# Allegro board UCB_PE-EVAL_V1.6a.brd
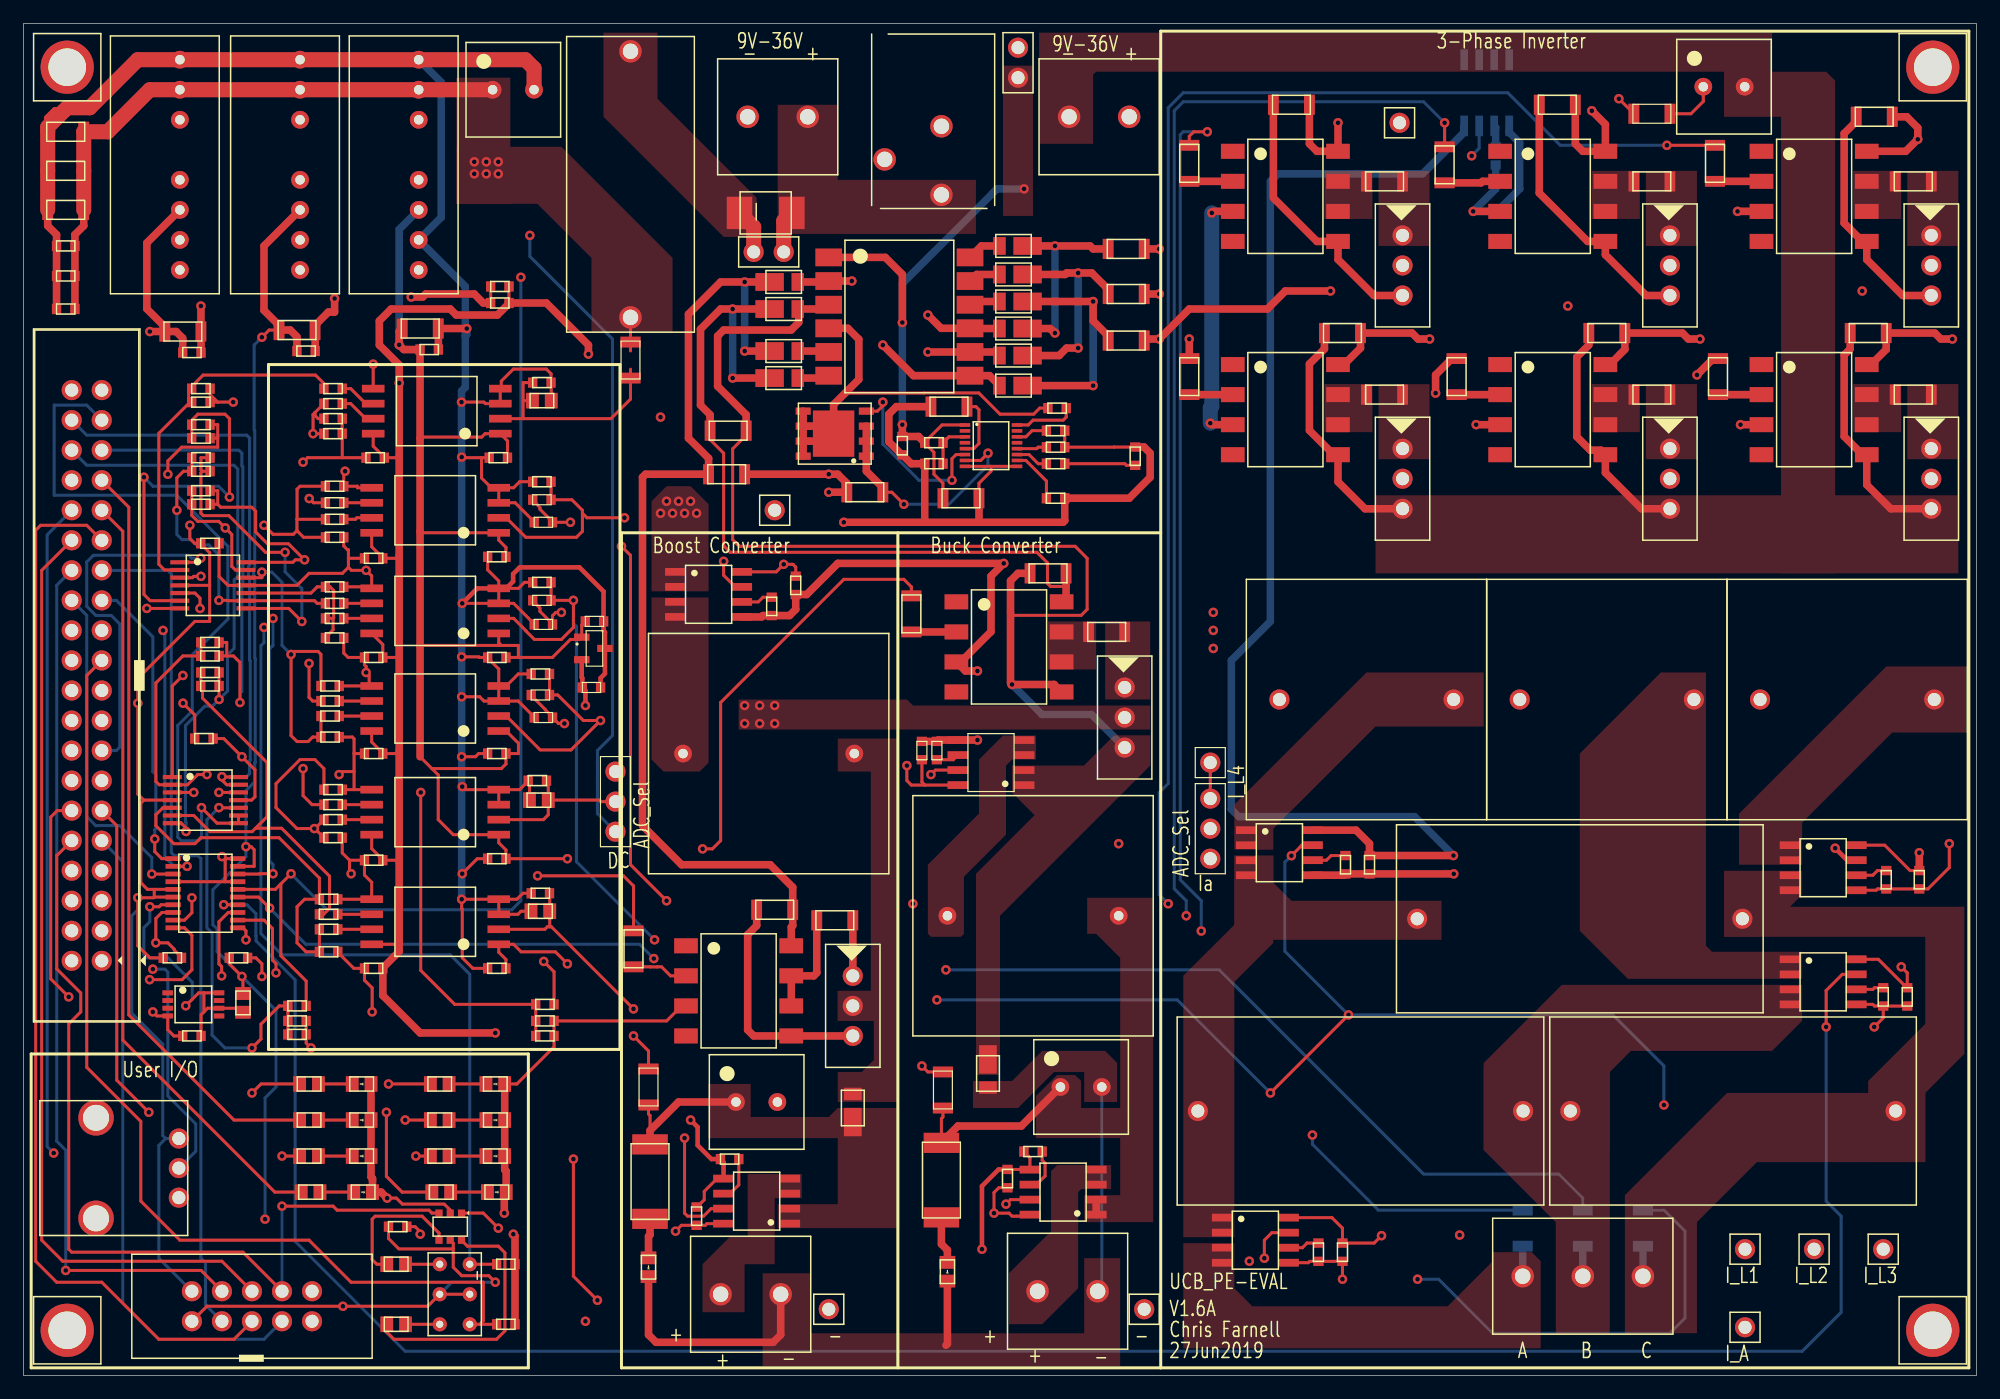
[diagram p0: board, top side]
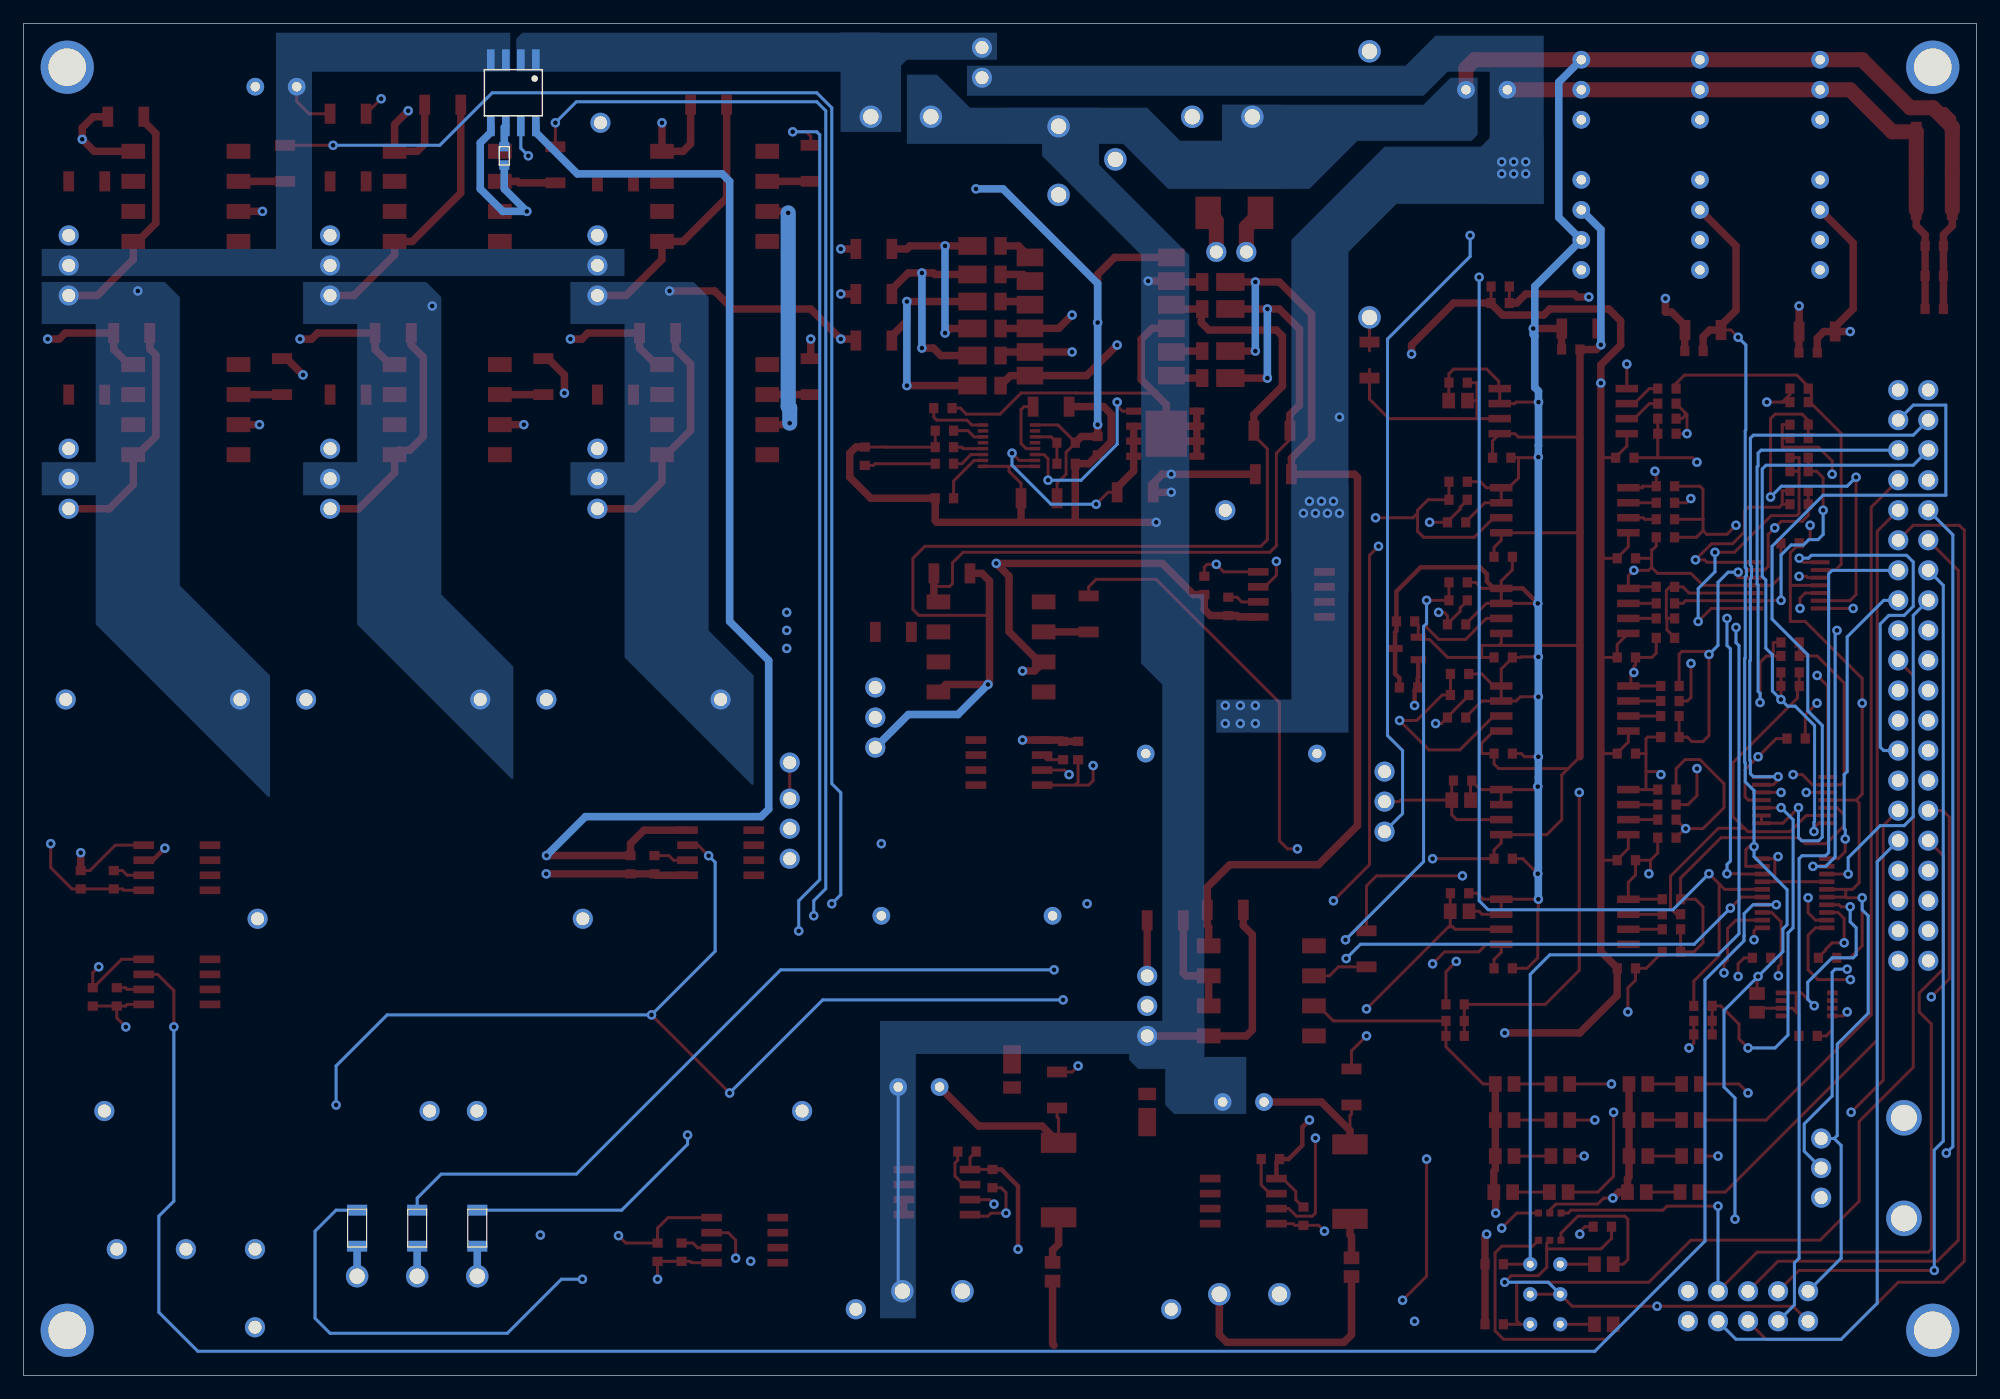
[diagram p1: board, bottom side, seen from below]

Outline 165.1 x 114.3 mm; copper layers: TOP, LAYER2, LAYER3, BOTTOM. Coordinates in mm from the lower left corner of the outline.
Outline path: 0,114.3 165.1,114.3 165.1,0 0,0 0,114.3

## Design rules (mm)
constraint set DEFAULT: min track width 0.254

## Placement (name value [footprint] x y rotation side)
ADC1  AD7928BRUZ  [20-TSSOP]  15.37 40.77 0 top
C1  10uF  [ECQ-E2106KFB]  113.03 22.35 0 top
C2  10uF  [ECQ-E2106KFB]  144.53 22.35 0 top
C3  10uF  [ECQ-E2106KFB]  131.57 38.61 0 top
C4  100uF  [UVZ1H101MPD]  89.41 24.38 0 top
C5  100uF  [UVZ1H101MPD]  41.4 108.71 0 top
C16  10uF  [C_1206]  79.25 74.17 0 top
C17  1uF  [C_0603]  74.3 78.61 270 top
C18  4.7uF  [C_1206]  78.23 81.91 180 top
C19  2.2nF  [C_0603]  87.25 74.17 180 top
C20  4.7nF  [C_0603]  93.98 77.72 270 top
C21  10uF  [C_1206]  93.22 87.5 0 top
C22  10uF  [C_1206]  93.22 91.44 0 top
C23  10uF  [C_1206]  93.22 95.25 0 top
C24  10uF  [C_1206]  59.56 79.88 0 top
C25  10uF  [C_1206]  59.44 76.2 0 top
C26  10uF  [C_1206]  3.56 105.16 180 top
C27  10uF  [C_1206]  3.56 101.85 180 top
C28  10uF  [C_1206]  13.46 88.26 0 top
C29  10uF  [C_1206]  23.11 88.39 0 top
C30  1uF  [C_0603]  3.56 92.96 180 top
C31  1uF  [C_0603]  3.56 95.5 180 top
C32  1uF  [C_0603]  23.88 86.61 0 top
C33  1uF  [C_0603]  14.22 86.49 0 top
C34  100uF  [UVZ1H101MPD]  143.76 108.97 0 top
C35  100uF  [UVZ1H101MPD]  61.98 23.11 0 top
C36  4.7uF  [C_1206]  107.19 107.44 180 top
C37  4.7uF  [C_1206]  129.67 107.44 180 top
C38  4.7uF  [C_1206]  156.46 106.43 180 top
C39  4.7uF  [C_1206]  86.61 67.82 180 top
C40  4.7uF  [C_1206]  111.51 88.14 180 top
C41  4.7uF  [C_1206]  133.86 88.14 180 top
C42  4.7uF  [C_1206]  155.96 88.14 180 top
C43  4.7uF  [C_1206]  63.5 39.37 180 top
C44  0.1uF  [C_0603]  111.51 10.41 270 top
C45  0.1uF  [C_0603]  160.27 41.91 270 top
C46  0.1uF  [C_0603]  159.26 32 270 top
C47  1nF  [C_0603]  109.47 10.41 270 top
C48  1nF  [C_0603]  111.76 43.18 270 top
C49  1nF  [C_0603]  157.23 32 270 top
C50  1nF  [C_0603]  85.34 18.92 180 top
C51  1nF  [C_0603]  59.69 18.29 180 top
C52  0.1uF  [C_0603]  83.19 16.64 90 top
C53  0.1uF  [C_0603]  56.9 13.46 90 top
C54  10uF  [C_1206]  3.56 98.55 180 top
C55  10uF  [C_1206]  33.53 88.52 0 top
C56  1uF  [C_0603]  3.56 90.17 180 top
C57  1uF  [C_0603]  34.29 86.74 0 top
C58  100pF  [C_0603]  43.81 83.95 0 top
C59  0.1uF  [C_0603]  40.13 77.6 180 top
C60  0.1uF  [C_0603]  29.72 77.6 180 top
C61  100pF  [C_0603]  14.99 82.3 0 top
C62  100pF  [C_0603]  26.16 79.63 180 top
C63  100pF  [C_0603]  43.81 75.56 180 top
C64  0.1uF  [C_0603]  40.01 69.22 180 top
C65  0.1uF  [C_0603]  29.59 69.09 180 top
C66  100pF  [C_0603]  14.99 79.25 0 top
C67  100pF  [C_0603]  26.29 70.87 180 top
C68  100pF  [C_0603]  43.81 67.06 180 top
C69  0.1uF  [C_0603]  40.01 60.71 180 top
C70  0.1uF  [C_0603]  29.59 60.71 180 top
C71  100pF  [C_0603]  14.99 76.45 0 top
C72  100pF  [C_0603]  26.29 62.36 180 top
C73  100pF  [C_0603]  43.69 59.31 180 top
C74  0.1uF  [C_0603]  40.01 52.58 180 top
C75  0.1uF  [C_0603]  29.59 52.58 180 top
C76  100pF  [C_0603]  14.99 73.66 0 top
C77  100pF  [C_0603]  25.91 53.98 180 top
C78  100pF  [C_0603]  43.43 50.29 180 top
C79  0.1uF  [C_0603]  40.01 43.69 180 top
C80  0.1uF  [C_0603]  29.59 43.56 180 top
C81  100pF  [C_0603]  15.75 60.83 0 top
C82  100pF  [C_0603]  26.16 45.47 180 top
C83  100pF  [C_0603]  43.69 40.77 180 top
C84  0.1uF  [C_0603]  40.01 34.42 180 top
C85  0.1uF  [C_0603]  29.59 34.42 180 top
C86  100pF  [C_0603]  15.75 58.29 0 top
C87  100pF  [C_0603]  25.78 35.81 180 top
C88  220pF  [C_0603]  23.11 28.83 0 top
C89  220pF  [C_0603]  44.07 28.7 0 top
C94  1nF  [C_0603]  124.46 103.12 270 bottom
C95  0.1uF  [C_0603]  40.26 92.07 180 top
C96  1uF  [C_0603]  12.57 35.31 0 top
C97  1uF  [C_0603]  18.16 35.31 0 top
C98  1uF  [C_0603]  15.75 70.36 0 top
C99  1uF  [C_0603]  15.24 53.85 0 top
C100  0.1uF  [C_0603]  40.26 90.68 180 top
C102  1uF  [C_0603]  14.22 28.7 0 top
C103  0.1uF  [C_0603]  31.62 12.57 0 top
C104  1nF  [C_0603]  157.48 41.91 270 top
C105  1nF  [C_0603]  63.25 65.02 270 top
C106  0.1uF  [C_0603]  65.28 66.8 270 top
C107  0.1uF  [C_0603]  113.79 43.18 270 top
C108  1nF  [C_0603]  77.22 52.83 90 top
C109  0.1uF  [C_0603]  75.95 52.83 90 top
C110  0.1uF  [C_0603]  48.01 58.17 0 top
C111  0.1uF  [C_0603]  48.26 63.75 0 top
C112  0.1uF  [C_0603]  43.94 72.14 180 top
C113  0.1uF  [C_0603]  43.94 63.5 180 top
C114  0.1uF  [C_0603]  43.94 55.63 180 top
D1  STPS3150U  [DO-214AA_SMB]  62.74 98.3 0 top
D5  DFLS260-7  [POWERDI-123]  83.69 90.81 180 top
D6  DFLS260-7  [POWERDI-123]  83.69 93.09 180 top
D7  DFLS260-7  [POWERDI-123]  83.69 95.5 180 top
D8  DFLS260-7  [POWERDI-123]  64.26 84.33 0 top
D9  DFLS260-7  [POWERDI-123]  64.26 86.61 0 top
D10  DFLZ18-7  [POWERDI-123]  83.69 83.69 180 top
D11  DFLZ18-7  [POWERDI-123]  83.69 86.23 180 top
D12  DFLZ18-7  [POWERDI-123]  83.69 88.52 180 top
D13  DFLZ18-7  [POWERDI-123]  64.26 90.17 0 top
D14  DFLZ18-7  [POWERDI-123]  64.26 92.46 0 top
D15  DFLS260-7  [POWERDI-123]  81.53 25.53 270 top
D16  DFLS260-7  [POWERDI-123]  70.1 22.61 90 top
D17  LED-R  [LED_0805-RED]  78.11 8.76 90 top
D18  LED-G  [LED_0805-GREEN]  52.83 9.14 90 top
D19  LED-G  [LED_0805-GREEN]  40.01 15.49 180 top
D20  LED-Y  [LED_0805-YELLOW]  39.88 18.54 180 top
D21  LED-O  [LED_0805-ORANGE]  39.88 21.59 180 top
D22  LED-R  [LED_0805-RED]  39.88 24.64 180 top
D23  LED-G  [LED_0805-GREEN]  28.7 15.49 180 top
D24  LED-Y  [LED_0805-YELLOW]  28.58 18.54 180 top
D25  LED-O  [LED_0805-ORANGE]  28.58 21.59 180 top
D26  LED-R  [LED_0805-RED]  28.58 24.64 180 top
F1  65600001009  [FUSE_5X20MM]  51.31 100.71 270 top
J1  AWHW 40G-0202-T  [40-IDC-M]  5.33 59.18 180 top
J2  -  [1715721]  63.75 106.43 270 top
J3  -  [1715734]  131.83 8.38 90 top
J4  -  [1715721]  88.27 7.11 90 top
J5  -  [1715721]  61.47 6.86 90 top
J6  PJ-102BH  [DC-PWR_JACK]  77.6 106.17 0 top
J7  AWHW 10G-0202-T  [10-IDC-M]  19.3 5.84 90 top
J8  -  [1715721]  90.93 106.43 270 top
JP1  -  [J_1X2]  84.07 111 180 top
JP2  -  [J_1X2]  62.99 95 270 top
JP3  -  [J_1X3]  100.33 46.23 180 top
JP4  -  [J_1X3]  50.04 48.51 0 top
L1  180uH  [PCV-2-184-05L]  113.54 57.15 0 top
L2  180uH  [PCV-2-184-05L]  133.86 57.15 0 top
L3  180uH  [PCV-2-184-05L]  154.18 57.15 0 top
L4  560uH  [PCV-2-564-02L]  85.34 38.86 0 top
L5  560uH  [PCV-2-564-02L]  62.99 52.58 0 top
MECH1  Mech_Hole  [4-40_SCREW]  3.68 110.62 0 top
MECH2  Mech_Hole  [4-40_SCREW]  3.68 3.81 0 top
MECH3  Mech_Hole  [4-40_SCREW]  161.42 110.62 0 top
MECH4  Mech_Hole  [4-40_SCREW]  161.42 3.81 0 top
PM1  EC4SAW-24S33N  [SIP-8]  22.1 102.36 0 top
PM2  EC4SAW-24S05N  [SIP-8]  11.94 102.36 0 top
PM3  EC4SAW-24S05N  [SIP-8]  32.13 102.36 0 top
Q1  STGP15H60DF  [TO-220]  116.59 93.85 0 top
Q2  STGP15H60DF  [TO-220]  116.59 75.82 0 top
Q3  STGP15H60DF  [TO-220]  139.19 93.85 0 top
Q4  STGP15H60DF  [TO-220]  139.19 75.82 0 top
Q5  STGP15H60DF  [TO-220]  161.29 93.85 0 top
Q6  STGP15H60DF  [TO-220]  161.29 75.82 0 top
Q7  STGP15H60DF  [TO-220]  93.09 55.63 0 top
Q8  STGP15H60DF  [TO-220]  70.1 31.24 0 top
Q9  Si7898DP  [SO-8_PP]  68.58 79.63 180 top
R8  825k  [R_0603]  76.96 78.87 0 top
R9  215k  [R_0603]  76.96 77.09 0 top
R10  133k  [R_0603]  87.25 78.49 180 top
R11  10k  [R_0603]  87.25 77.09 180 top
R12  71.5k  [R_0603]  87.38 81.79 180 top
R13  6.04k  [R_0603]  87.25 79.88 0 top
R14  0.01  [R_1206]  71.12 74.68 0 top
R15  2.49k  [R_2512]  77.6 16.51 270 top
R16  2.49k  [R_2512]  52.96 16.38 270 top
R17  120  [R_1206]  98.55 102.49 270 top
R18  10  [R_1206]  115.06 100.97 0 top
R19  120  [R_1206]  120.14 102.36 270 top
R20  10  [R_1206]  137.67 100.97 0 top
R21  120  [R_1206]  143 102.49 270 top
R22  10  [R_1206]  159.77 100.97 0 top
R23  120  [R_1206]  75.06 64.39 270 top
R24  10  [R_1206]  91.57 62.87 0 top
R25  120  [R_1206]  98.55 84.46 270 top
R26  10  [R_1206]  115.06 82.93 0 top
R27  120  [R_1206]  121.16 84.46 270 top
R28  10  [R_1206]  137.67 82.93 0 top
R29  120  [R_1206]  143.26 84.46 270 top
R30  10  [R_1206]  159.77 82.93 0 top
R31  120  [R_1206]  51.56 36.07 270 top
R32  10  [R_1206]  68.58 38.48 0 top
R33  1Meg  [R_1206]  51.31 85.85 270 top
R35  10k  [R_0603]  26.16 82.17 180 top
R36  10k  [R_0603]  26.16 83.44 180 top
R37  10k  [R_0603]  26.16 80.9 180 top
R38  10k  [R_0603]  14.99 83.44 0 top
R39  31.6k  [R_0805]  43.81 82.42 0 top
R40  1Meg  [R_1206]  126.75 12.45 90 bottom
R41  10k  [R_0603]  26.29 72.39 180 top
R42  10k  [R_0603]  26.29 73.79 180 top
R43  10k  [R_0603]  26.29 75.18 180 top
R44  10k  [R_0603]  14.99 80.39 0 top
R45  13.7k  [R_0603]  43.81 74.04 180 top
R46  1Meg  [R_1206]  131.83 12.45 90 bottom
R47  10k  [R_0603]  26.29 64.01 180 top
R48  10k  [R_0603]  26.29 65.28 180 top
R49  10k  [R_0603]  26.29 66.68 180 top
R50  10k  [R_0603]  14.99 77.6 0 top
R51  13.7k  [R_0603]  43.81 65.53 180 top
R52  1Meg  [R_1206]  136.91 12.45 90 bottom
R53  10k  [R_0603]  25.91 55.75 180 top
R54  10k  [R_0603]  25.91 57.02 180 top
R55  10k  [R_0603]  25.91 58.29 180 top
R56  10k  [R_0603]  14.99 74.8 0 top
R57  13.7k  [R_0603]  43.69 57.53 180 top
R58  1Meg  [R_1206]  77.72 24.13 270 top
R59  10k  [R_0603]  26.16 46.99 180 top
R60  10k  [R_0603]  26.16 48.26 180 top
R61  10k  [R_0603]  26.16 49.53 180 top
R62  10k  [R_0603]  15.75 61.98 0 top
R63  31.6k  [R_0805]  43.56 48.64 180 top
R64  1Meg  [R_1206]  52.83 24.38 90 top
R65  10k  [R_0603]  25.78 37.72 180 top
R66  10k  [R_0603]  25.78 38.99 180 top
R67  10k  [R_0603]  25.78 40.26 180 top
R68  10k  [R_0603]  15.75 59.44 0 top
R69  31.6k  [R_0805]  43.69 39.24 180 top
R70  10k  [R_0603]  23.11 31.24 180 top
R71  15k  [R_0603]  23.11 29.97 0 top
R72  10k  [R_0603]  44.07 31.37 180 top
R73  15k  [R_0603]  44.07 29.97 0 top
R74  PTV09A-4020F-B103  [9MM_POT]  7.62 17.53 180 top
R75  1k  [R_0805]  18.54 31.5 270 top
R76  330  [R_0805]  31.5 4.32 0 top
R77  330  [R_0805]  31.5 9.4 0 top
R78  10k  [R_0603]  40.77 9.4 0 top
R79  10k  [R_0603]  40.77 4.32 0 top
R80  220  [R_0805]  35.31 15.49 0 top
R81  220  [R_0805]  35.18 18.54 0 top
R82  220  [R_0805]  35.18 21.59 0 top
R83  220  [R_0805]  35.18 24.64 0 top
R84  220  [R_0805]  24.26 15.49 0 top
R85  220  [R_0805]  24.13 18.54 0 top
R86  220  [R_0805]  24.13 21.59 0 top
R87  220  [R_0805]  24.13 24.64 0 top
R88  1Meg  [R_1206]  137.67 106.68 0 top
SW8  G13JPCF  [G13JPCF_TH]  36.45 6.86 0 top
TP1  TP-Y  [TP-YELLOW]  116.33 105.92 0 top
TP2  TP-Y  [TP-YELLOW]  145.54 4.06 0 top
TP3  TP-Y  [TP-YELLOW]  145.54 10.67 0 top
TP4  TP-Y  [TP-YELLOW]  151.38 10.67 0 top
TP5  TP-Y  [TP-YELLOW]  157.23 10.67 0 top
TP6  TP-Y  [TP-YELLOW]  63.5 73.15 0 top
TP7  TP-Y  [TP-YELLOW]  68.07 5.59 0 top
TP8  TP-Y  [TP-YELLOW]  94.74 5.59 0 top
TP9  TP-Y  [TP-YELLOW]  100.33 51.82 0 top
TX1  VP1-0102-R  [TX-VP1]  74.04 89.53 0 top
U1  ACS714LLCTR-05B-T  [8-SOIC]  104.14 11.43 0 top
U3  LT3748EMS#PBF-ND  [16-MSOP]  81.79 78.61 0 top
U4  ACS714LLCTR-05B-T  [8-SOIC]  106.17 44.2 0 top
U5  ACS714LLCTR-05B-T  [8-SOIC]  152.15 33.27 0 top
U6  ACS714LLCTR-05B-T  [8-SOIC]  87.88 15.49 180 top
U7  ACS714LLCTR-05B-T  [8-SOIC]  61.98 14.73 180 top
U8  HCPL-3120-300E  [8-DIP_GW]  106.68 99.69 0 top
U9  HCPL-3120-300E  [8-DIP_GW]  129.29 99.69 0 top
U10  HCPL-3120-300E  [8-DIP_GW]  151.38 99.69 0 top
U11  HCPL-3120-300E  [8-DIP_GW]  83.31 61.6 0 top
U12  HCPL-3120-300E  [8-DIP_GW]  106.68 81.66 0 top
U13  HCPL-3120-300E  [8-DIP_GW]  129.29 81.66 0 top
U14  HCPL-3120-300E  [8-DIP_GW]  151.38 81.66 0 top
U15  HCPL-3120-300E  [8-DIP_GW]  60.45 32.51 0 top
U16  OPA4322AIPWR  [OPA4332_14-TSSOP]  16 66.8 0 top
U17  OPA4322AIPWR  [OPA4332_14-TSSOP]  15.37 48.64 0 top
U20  ACPL-C87B  [ACPL-C87X]  34.92 81.53 180 top
U21  ACPL-C87B  [ACPL-C87X]  34.8 73.15 180 top
U22  ACPL-C87B  [ACPL-C87X]  34.8 64.64 180 top
U23  ACPL-C87B  [ACPL-C87X]  34.8 56.39 180 top
U24  ACPL-C87B  [ACPL-C87X]  34.8 47.62 180 top
U25  ACPL-C87B  [ACPL-C87X]  34.8 38.35 180 top
U26  ACS714LLCTR-05B-T  [8-SOIC]  123.7 108.46 270 bottom
U27  LT1009CZ  [8-MSOP]  14.35 31.37 0 top
U28  SN74LVC2G07DBVR  [SOT-23-6]  36.07 12.57 270 top
U29  ACS714LLCTR-05B-T  [8-SOIC]  152.15 42.93 0 top
U30  ACS714LLCTR-05B-T  [8-SOIC]  57.91 66.04 0 top
U31  ACS714LLCTR-05B-T  [8-SOIC]  81.79 51.82 180 top
U32  ISL21080  [SOT_23-3]  48.26 61.47 0 top

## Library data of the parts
ADC1 = AD7928BRUZ
C1-C3 C16-C33 C36-C89 C94-C100 C102-C114 = CAP NP
C4 C5 C34 C35 = CAP P
D1 D5-D9 D15 D16 = D-Schottky
D10-D14 = D-Zener
D17-D26 = LED
F1 = FUSEHOLDER
J1 = Header_2x20
J2 J4 J5 J8 = Connector-2
J3 = Connector-3
J6 = DC-Jack_3
J7 = Header_2x5
JP1 JP2 = JP2
JP3 JP4 = JP3
L1-L5 = Ind
MECH1-MECH4 = Mech_Hole
PM1-PM3 = EC4SA
Q1-Q8 = IGBT_TO220
Q9 = N-FET_Si7898DP
R8-R33 R35-R73 R75-R88 = R-Standard
R74 = R-POT
SW8 = SW_G13JPCF
TP1-TP9 = TP
TX1 = TX_VP1-0102-R
U1 U4-U7 U26 U29-U31 = ACS714
U3 = LT3748EMS#PBF-ND
U8-U15 = HCPL-3120
U16 U17 = OPA4322AIPWR
U20-U25 = ACPL-C87B
U27 = LT1009CZ
U28 = SN74LVC2G07DBV
U32 = ISL21080

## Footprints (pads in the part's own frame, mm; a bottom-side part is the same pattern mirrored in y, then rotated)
4-40_SCREW
  round 4.5 hole 3.175: 1(0,0)
8-DIP_GW
  rect 2x1.27 smd: 1(-4.45,3.81) 2(-4.45,1.27) 3(-4.45,-1.27) 4(-4.45,-3.81) 5(4.45,-3.81) 6(4.45,-1.27) 7(4.45,1.27) 8(4.45,3.81)
8-MSOP
  rect 0.889x0.42 smd: 1(-2.17,0.975) 2(-2.17,0.325) 3(-2.17,-0.325) 4(-2.17,-0.975) 5(2.17,-0.975) 6(2.17,-0.325) 7(2.17,0.325) 8(2.17,0.975)
8-SOIC
  rect 1.75x0.65 smd: 1(-2.8,1.905) 2(-2.8,0.635) 3(-2.8,-0.635) 4(-2.8,-1.905) 5(2.8,-1.905) 6(2.8,-0.635) 7(2.8,0.635) 8(2.8,1.905)
9MM_POT
  round 3 hole 2.2: (1.5,4.25) (1.5,-4.25)
  round 1.7 hole 1.1: 1(-5.5,2.5) 2(-5.5,0) 3(-5.5,-2.5)
10-IDC-M
  round 1.7 hole 1.1: 1(-1.27,5.08) 2(1.27,5.08) 3(-1.27,2.54) 4(1.27,2.54) 5(-1.27,0) 6(1.27,0) 7(-1.27,-2.54) 8(1.27,-2.54) 9(-1.27,-5.08) 10(1.27,-5.08)
16-MSOP
  rect 0.89x0.305 smd: 1(-2.2,1.75) 2(-2.2,1.25) 3(-2.2,0.75) 4(-2.2,0.25) 5(-2.2,-0.25) 6(-2.2,-0.75) 7(-2.2,-1.25) 8(-2.2,-1.75) 9(2.2,-1.75) 10(2.2,-1.25) 11(2.2,-0.75) 12(2.2,-0.25) 13(2.2,0.25) 14(2.2,0.75) 15(2.2,1.25) 16(2.2,1.75)
20-TSSOP
  rect 1.3x0.4 smd: 1(-2.725,2.925) 2(-2.725,2.275) 3(-2.725,1.625) 4(-2.725,0.975) 5(-2.725,0.325) 6(-2.725,-0.325) 7(-2.725,-0.975) 8(-2.725,-1.625) 9(-2.725,-2.275) 10(-2.725,-2.925) 11(2.725,-2.925) 12(2.725,-2.275) 13(2.725,-1.625) 14(2.725,-0.975) 15(2.725,-0.325) 16(2.725,0.325) 17(2.725,0.975) 18(2.725,1.625) 19(2.725,2.275) 20(2.725,2.925)
40-IDC-M
  round 1.7 hole 1.1: 1(-1.27,24.13) 2(1.27,24.13) 3(-1.27,21.59) 4(1.27,21.59) 5(-1.27,19.05) 6(1.27,19.05) 7(-1.27,16.51) 8(1.27,16.51) 9(-1.27,13.97) 10(1.27,13.97) 11(-1.27,11.43) 12(1.27,11.43) 13(-1.27,8.89) 14(1.27,8.89) 15(-1.27,6.35) 16(1.27,6.35) 17(-1.27,3.81) 18(1.27,3.81) 19(-1.27,1.27) 20(1.27,1.27) 21(-1.27,-1.27) 22(1.27,-1.27) 23(-1.27,-3.81) 24(1.27,-3.81) 25(-1.27,-6.35) 26(1.27,-6.35) 27(-1.27,-8.89) 28(1.27,-8.89) 29(-1.27,-11.43) 30(1.27,-11.43) 31(-1.27,-13.97) 32(1.27,-13.97) 33(-1.27,-16.51) 34(1.27,-16.51) 35(-1.27,-19.05) 36(1.27,-19.05) 37(-1.27,-21.59) 38(1.27,-21.59) 39(-1.27,-24.13) 40(1.27,-24.13)
1715721
  round 1.9 hole 1.3: 1(0,2.54) 2(0,-2.54)
1715734
  round 1.9 hole 1.3: 1(0,5.08) 2(0,0) 3(0,-5.08)
ACPL-C87X
  rect 1.905x0.64 smd: 1(-5.372,1.905) 2(-5.372,0.635) 3(-5.372,-0.635) 4(-5.372,-1.905) 5(5.372,-1.905) 6(5.372,-0.635) 7(5.372,0.635) 8(5.372,1.905)
C_0603
  rect 0.787x0.864 smd: 1(-0.775,0) 2(0.775,0)
C_1206
  rect 0.914x1.702 smd: 1(-1.524,0) 2(1.524,0)
DC-PWR_JACK
  round 1.9 hole 1.3: 1(0,-6.35) 2(0,-0.55) 3(-4.8,-3.35)
DO-214AA_SMB
  rect 2.159x2.743 smd: 1(-2.21,0) 2(2.21,0)
ECQ-E2106KFB
  round 1.7 hole 1.1: 1(-13.75,0) 2(13.75,0)
FUSE_5X20MM
  round 1.9 hole 1.3: 1(-11.25,0) 2(11.25,0)
G13JPCF_TH
  round 1.2 hole 0.6: 1(1.27,2.54) 2(1.27,0) 3(1.27,-2.54) 4(-1.27,2.54) 5(-1.27,0) 6(-1.27,-2.54)
J_1X2
  round 1.7 hole 1.1: 1(0,1.27) 2(0,-1.27)
J_1X3
  round 1.7 hole 1.1: 1(0,2.54) 2(0,0) 3(0,-2.54)
LED_0805-GREEN
  rect 1.08x1.321 smd: 1(-0.794,0) 2(0.794,0)
LED_0805-ORANGE
  rect 1.08x1.321 smd: 1(-0.794,0) 2(0.794,0)
LED_0805-RED
  rect 1.08x1.321 smd: 1(-0.794,0) 2(0.794,0)
LED_0805-YELLOW
  rect 1.08x1.321 smd: 1(-0.794,0) 2(0.794,0)
OPA4332_14-TSSOP
  rect 1.6x0.35 smd: 1(-2.8,1.95) 2(-2.8,1.3) 3(-2.8,0.65) 4(-2.8,0) 5(-2.8,-0.65) 6(-2.8,-1.3) 7(-2.8,-1.95) 8(2.8,-1.95) 9(2.8,-1.3) 10(2.8,-0.65) 11(2.8,0) 12(2.8,0.65) 13(2.8,1.3) 14(2.8,1.95)
PCV-2-184-05L
  round 1.7 hole 1.1: 1(-7.365,0) 2(7.365,0)
PCV-2-564-02L
  round 1.5 hole 0.8: 1(-7.24,0) 2(7.24,0)
POWERDI-123
  rect 2.4x1.5 smd: 1(-1.188,0)
  rect 1.05x1.5 smd: 2(1.188,0)
R_0603
  rect 0.787x0.864 smd: 1(-0.775,0) 2(0.775,0)
R_0805
  rect 1.08x1.321 smd: 1(-0.794,0) 2(0.794,0)
R_1206
  rect 0.914x1.702 smd: 1(-1.524,0) 2(1.524,0)
R_2512
  rect 1.7x3 smd: 1(-3.15,0) 2(3.15,0)
SIP-8
  round 1.5 hole 0.8: 1(1.27,8.89) 2(1.27,6.35) 3(1.27,3.81) 5(1.27,-1.27) 6(1.27,-3.81) 7(1.27,-6.35) 8(1.27,-8.89)
SO-8_PP
  rect 1.27x0.61 smd: 1(-2.67,1.905) 2(-2.67,0.635) 3(-2.67,-0.635) 4(-2.67,-1.905) 5(2.67,-1.905) 6(2.67,-0.635) 7(2.67,0.635) 8(2.67,1.905)
  rect 3.5x3.91 smd: 9(0.1,0)
SOT-23-6
  rect 0.6x0.6 smd: 1(-1.15,0.95) 2(-1.15,0) 3(-1.15,-0.95) 4(1.15,-0.95) 5(1.15,0) 6(1.15,0.95)
SOT_23-3
  rect 1.3x0.6 smd: 1(-1.075,0.95) 2(-1.075,-0.95) 3(0.889,0)
TO-220
  round 1.7 hole 1.1: 1(0,2.54) 2(0,0) 3(0,-2.54)
TP-YELLOW
  round 1.7 hole 1.1: 1(0,0)
TX-VP1
  rect 2.25x1.5 smd: 1(-5.975,5) 2(-5.975,3) 3(-5.975,1) 4(-5.975,-1) 5(-5.975,-3) 6(-5.975,-5) 7(5.975,-5) 8(5.975,-3) 9(5.975,-1) 10(5.975,1) 11(5.975,3) 12(5.975,5)
UVZ1H101MPD
  round 1.5 hole 0.8: 1(-1.75,0) 2(1.75,0)

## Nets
0V9: C110.1 C112.1 C113.1 C114.1 R45.2 R51.2 R57.2 U32.2(V_OUT)
3V3_ISO: ADC1.19 C29.1 C32.1 C97.1 C103.1 J7.1 PM1.6 R75.1 SW8.2 SW8.5 U28.5(VCC)
5V: C55.1 C57.1 C59.1 C64.1 C69.1 C74.1 C79.1 C84.1 C111.1 PM3.6 U20.1 U21.1 U22.1 U23.1 U24.1 U25.1 U32.1
5V_ISO: ADC1.5 ADC1.6 C28.1 C33.1 C44.1 C45.1 C46.1 C52.1 C53.1 C60.1 C65.1 C70.1 C75.1 C80.1 C85.1 C95.1 C96.1 C98.1 C99.1 C100.1 C106.1 C107.1 C109.1 J7.2 PM2.6 R74.3 U1.8 U4.8 U5.8 U6.8 U7.8 U16.4 U17.4 U20.8 U21.8 U22.8 U23.8 U24.8 U25.8 U26.8 U29.8 U30.8 U31.8
18V_G1: C21.1 C36.1 D5.1 D10.1 U8.8
18V_G3: C22.1 C37.1 D6.1 D11.1 U9.8
18V_G5: C23.1 C38.1 D7.1 D12.1 U10.8
18V_G7: C24.1 C39.1 D8.1 D13.1 U11.8
18V_GL: C25.1 C40.1 C41.1 C42.1 C43.1 D9.1 D14.1 U12.8 U13.8 U14.8 U15.8
GND: C4.2 C5.2 C16.2 C17.2 C18.2 C19.1 C20.1 C25.2 C26.2 C27.2 C30.2 C31.2 C34.2 C35.2 C40.2 C41.2 C42.2 C43.2 C54.2 C55.2 C56.2 C57.2 C58.2 C59.2 C63.2 C64.2 C68.2 C69.2 C73.2 C74.2 C78.2 C79.2 C83.2 C84.2 C110.2 C111.2 C112.2 C113.2 C114.2 D14.2 D15.2 D17.1(CATHODE) D18.1(CATHODE) J2.2(P2) J4.2(P2) J5.2(P2) J6.2 J8.2(P2) PM1.1 PM2.1 PM3.1 PM3.7 Q2.3 Q4.3 Q6.3 Q8.3 R9.1 R10.1 R13.2 R14.1 R39.2 R63.2 R69.2 TX1.2 U3.8 U3.9 U12.5 U13.5 U14.5 U15.5 U20.3 U20.4 U21.3 U21.4 U22.3 U22.4 U23.3 U23.4 U24.3 U24.4 U25.3 U25.4 U32.3
GND_SIGNAL: ADC1.4 ADC1.8 ADC1.17 ADC1.20 C28.2 C29.2 C32.2 C33.2 C44.2 C45.2 C46.2 C47.2 C48.2 C49.2 C50.2 C51.2 C52.2 C53.2 C60.2 C62.1 C65.2 C67.1 C70.2 C72.1 C75.2 C77.1 C80.2 C82.1 C85.2 C87.1 C88.2 C89.2 C94.2 C95.2 C96.2 C97.2 C98.2 C99.2 C100.2 C102.1 C103.2 C104.2 C105.2 C106.2 C107.2 C108.2 C109.2 D19.1(CATHODE) D20.1(CATHODE) D21.1(CATHODE) D22.1(CATHODE) D23.1(CATHODE) D24.1(CATHODE) D25.1(CATHODE) D26.1(CATHODE) J1.20 J1.40 J7.9 J7.10 PM1.7 PM2.7 R37.1 R43.1 R49.1 R55.1 R61.1 R67.1 R71.2 R73.2 R74.1 R78.2 R79.2 U1.5 U4.5 U5.5 U6.5 U7.5 U8.3 U9.3 U10.3 U11.3 U12.3 U13.3 U14.3 U15.3 U16.11(V-) U17.11(V-) U20.5 U21.5 U22.5 U23.5 U24.5 U25.5 U26.5 U27.4 U28.2 U29.5 U30.5 U31.5
VIN: C5.1 C16.1 C17.1 C26.1 C27.1 C30.1 C31.1 C54.1 C56.1 F1.2 JP1.1 PM1.2 PM2.2 PM3.2 Q7.2 R8.1 R33.1 TX1.1 U3.1(VIN) U30.1 U30.2
ADC-IIN-3V: J1.37 U17.8 U17.9
ADC-VIN: C61.2 J1.15 R38.2 U16.1
ADC-VPOT-3V: J1.38 U17.13 U17.14
ADC_DSP4: C81.2 J1.35 R62.2 U17.1
ADC_VA: C66.2 J1.16 R44.2 U16.7
ADC_VB: C71.2 J1.17 R50.2 U16.8
ADC_VBOOST: C86.2 J1.36 R68.2 U17.7
ADC_VC: C76.2 J1.18 R56.2 U16.14
DC_LINK: C34.1 Q1.2 Q3.2 Q5.2 R88.2 U26.3 U26.4
DSP_G1: J1.1 R17.1
DSP_G2: J1.2 R25.1
DSP_G3: J1.3 R19.1
DSP_G4: J1.4 R27.1
DSP_G5: J1.5 R21.1
DSP_G6: J1.6 R29.1
DSP_G7: J1.7 R23.1
DSP_G8: J1.8 R31.1
GPIO-20: J1.27 J7.3
GPIO-21: J1.28 J7.4
GPIO-22: J1.29 J7.5
GPIO-23: J1.30 J7.6
I_BOOST: ADC1.11 TP7.1 U7.7(VOUT)
I_BUCK: ADC1.12 TP8.1 U6.7(VOUT)
I_L1: ADC1.15 TP3.1 U4.7(VOUT)
I_L2: ADC1.14 TP4.1 U5.7(VOUT)
I_L3: ADC1.13 TP5.1 U29.7(VOUT)
I_L4: JP3.3 TP9.1 U31.7(VOUT)
I_L5: ADC1.9(VIN7) TP6.1 U30.7(VOUT)
IA: JP3.1 TP2.1 U1.7(VOUT)
IGBT_G1: Q1.1(G) R18.2
IGBT_G2: Q2.1(G) R26.2
IGBT_G3: Q3.1(G) R20.2
IGBT_G4: Q4.1(G) R28.2
IGBT_G5: Q5.1(G) R22.2
IGBT_G6: Q6.1(G) R30.2
IGBT_G7: Q7.1(G) R24.2
IGBT_G8: Q8.1(G) R32.2
IIN: ADC1.16 R70.1 TP1.1 U26.7(VOUT)
LED1: J1.11 R80.1
LED2: J1.12 R81.1
LED3: J1.13 R82.1
LED4: J1.14 R83.1
LED5: J1.31 R84.1
LED6: J1.32 R85.1
LED7: J1.33 R86.1
LED8: J1.34 R87.1
LED9: J1.9 J7.7 U28.1
LED10: J1.10 J7.8 U28.3
SPI-ADC-VIN6: ADC1.10 JP3.2
SPI_CS: ADC1.3 J1.26
SPI_DIN: ADC1.2 J1.23
SPI_DOUT: ADC1.18 J1.24
SPI_SCLK: ADC1.1 J1.25
SW_1: J1.21 R79.1 SW8.3
SW_2: J1.22 R78.1 SW8.1(NO)
V_ADC4: C78.1 JP4.2 R63.1 U24.2
V_BOOST: C35.1 D16.1 R16.1 R64.1 U7.1 U7.2
V_BUCK: C4.1 L4.2 R15.1 R58.2 U6.1 U6.2
V_L1: C1.1 C3.1 U1.1 U1.2 U4.3 U4.4
V_L2: C1.2 C2.1 J3.2 R46.1 U5.3 U5.4
V_L3: C2.2 C3.2 J3.3(P3) R52.1 U29.3 U29.4
VA: J3.1 R40.1 U1.3 U1.4
VBK_SRC: C24.2 C39.2 D13.2 D15.1 Q7.3 TX1.3 U11.5 U31.1 U31.2
VMID1: C21.2 C36.2 D10.2 L1.1 Q1.3 Q2.2 TX1.7 U8.5
VMID2: C22.2 C37.2 D11.2 L2.1 Q3.3 Q4.2 TX1.8 U9.5
VMID3: C23.2 C38.2 D12.2 L3.1 Q5.3 Q6.2 TX1.9 U10.5
VPOT: R72.1 R74.2(WIPER)
N07970: R8.2 R9.2 U3.3
N08403: C18.1 U3.5
N08410: R10.2 U3.12
N08443: C19.2 U3.10
N08455: R11.2 U3.11
N08467: C20.2 R11.1
N09759: Q9.1 Q9.2 Q9.3(S3) R14.2 U3.7
N09873: Q9.5 Q9.6 Q9.7 Q9.8 Q9.9 R12.2 TX1.4
N10901: Q9.4 U3.6
N10913: R12.1 U3.16
N10917: R13.1 U3.14
N11491: D7.2 TX1.12
N11495: D6.2 TX1.11
N11499: D5.2 TX1.10
N11507: D8.2 TX1.6
N11532: D9.2 TX1.5
N38522: D17.2 R15.2
N38590: D16.2 L5.2 Q8.2
N38634: D18.2 R16.2
N38702: J4.1 U6.3 U6.4
N38762: J5.1 U7.3 U7.4
N41110: C50.1 U6.6
N41352: C51.1 U7.6
N42617: D1.2 J2.1 J6.1 JP2.1
N42649: D1.1 F1.1 JP2.2
N48243: C62.2 R35.2 R37.2 U16.3
N48256: R35.1 U20.7
N48260: R36.1 U20.6(VOUT-)
N48264: C61.1 R36.2 R38.1 U16.2
N48807: C58.1 R33.2 R39.1 U20.2
N51115: C67.2 R41.2 R43.2 U16.5
N51119: R41.1 U21.7
N51123: R42.1 U21.6(VOUT-)
N51127: C66.1 R42.2 R44.1 U16.6
N51265: C63.1 R40.2 R45.1 U21.2
N52251: C72.2 R47.2 R49.2 U16.10
N52255: R47.1 U22.7
N52259: R48.1 U22.6(VOUT-)
N52263: C71.1 R48.2 R50.1 U16.9
N52429: C68.1 R46.2 R51.1 U22.2
N53429: C77.2 R53.2 R55.2 U16.12
N53433: R53.1 U23.7
N53437: R54.1 U23.6(VOUT-)
N53441: C76.1 R54.2 R56.1 U16.13
N53607: C73.1 R52.2 R57.1 U23.2
N54653: C82.2 R59.2 R61.2 U17.3
N54657: R59.1 U24.7
N54661: R60.1 U24.6(VOUT-)
N54665: C81.1 R60.2 R62.1 U17.2
N56809: C87.2 R65.2 R67.2 U17.5
N56813: R65.1 U25.7
N56817: R66.1 U25.6(VOUT-)
N56821: C86.1 R66.2 R68.1 U17.6
N56959: C83.1 R64.2 R69.1 U25.2
N58569: C88.1 R70.2 R71.1 U17.10
N59411: C89.1 R72.2 R73.1 U17.12
N62015: C94.1 U26.6
N62666: J8.1 JP1.2 U26.1 U26.2
N71004: ADC1.7 C102.2 R75.2 U27.6(V+.) U27.8
N72702: R76.2 SW8.6
N72714: R77.2 SW8.4
N72726: R77.1 U28.4
N72730: R76.1 U28.6
N126025: D19.2 R80.2
N126027: D25.2 R86.2
N126029: D24.2 R85.2
N126031: D23.2 R84.2
N126033: D22.2 R83.2
N126035: D26.2 R87.2
N126037: D21.2 R82.2
N126039: D20.2 R81.2
N176335: C47.1 U1.6
N176535: C48.1 U4.6
N176547: C49.1 U5.6
N176863: L2.2 U5.1 U5.2
N176875: L3.2 U29.1 U29.2
N176963: L1.2 U4.1 U4.2
N179536: R17.2 U8.2
N179562: R18.1 U8.6 U8.7(V_OUT.)
N179712: R19.2 U9.2
N179754: R20.1 U9.6 U9.7(V_OUT.)
N179920: R21.2 U10.2
N179946: R22.1 U10.6 U10.7(V_OUT.)
N180096: R23.2 U11.2
N180138: R24.1 U11.6 U11.7(V_OUT.)
N180288: R25.2 U12.2
N180330: R26.1 U12.6 U12.7(V_OUT.)
N180476: R27.2 U13.2
N180502: R28.1 U13.6 U13.7(V_OUT.)
N180632: R29.2 U14.2
N180674: R30.1 U14.6 U14.7(V_OUT.)
N180804: R31.2 U15.2
N180846: R32.1 U15.6 U15.7(V_OUT.)
N220911: C104.1 U29.6
N223775: C105.1 U30.6
N223929: L5.1 U30.3 U30.4
N248745: C108.1 U31.6
N249090: L4.1 U31.3 U31.4
N283243: JP4.3 R88.1
N283252: JP4.1 R58.1

Pads without a net: J1 19 39; J6 3; MECH1 1; MECH2 1; MECH3 1; MECH4 1; PM1 3 5 8; PM2 3 5 8; PM3 3 5 8; U3 2 4 13 15; U8 1 4; U9 1 4; U10 1 4; U11 1 4; U12 1 4; U13 1 4; U14 1 4; U15 1 4; U27 1 2 3 5 7

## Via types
v1: diameter 0.8, hole 0.4, TOP to BOTTOM, 247 vias

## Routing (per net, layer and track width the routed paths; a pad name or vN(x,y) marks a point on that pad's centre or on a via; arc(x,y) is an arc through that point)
0V9: length 37.5
  TOP w0.254: v1(46.23,72.14) C112.1 44.72,72.17 43.65,73.24 43.65,73.39 43.04,74 R45.2 ; R57.2 42.91,57.49 44.11,56.3 44.11,56.27 44.72,55.66 C114.1 45.22,55.12 v1(45.72,55.12) ; C113.1 44.72,63.54 ; 44.72,63.54 44.72,64.24 45,64.52 v1(45.47,64.52) ; 44.72,63.54 43.65,64.61 43.65,64.88 43.04,65.49 R51.2
  TOP w0.381: v1(47.5,56.64) 47.5,57.9 C110.1 47.23,58.97 47.19,59.01 U32.2
  LAYER2 w0.254: v1(45.47,64.52) 46.99,64.52 47.75,65.28 ; v1(45.72,55.12) 46.27,55.67 46.53,55.67 v1(47.5,56.64)
  LAYER2 w0.381: v1(46.23,72.14) 46.23,67.82 47.75,66.29 47.75,57.74 47.5,57.49 v1(47.5,56.64)
3V3_ISO: length 155.7
  TOP w0.254: v1(18.8,44.7) 19.23,44.7 19.49,44.45 19.49,43.04 ADC1.19 ; 36.32,10.7 31.72,10.7 30.85,11.57 C103.1 ; 36.32,10.7 36.32,9.14 37.04,8.43 39.33,8.43 v1(39.88,7.87) ; 36.32,10.7 36.32,11.17 U28.5 ; 37.72,6.86 SW8.5 34.16,5.84 v1(26.99,5.84) 15.49,5.84 J7.1 ; v1(20.14,87.78) 20.75,88.39 C29.1 ; C97.1 17.39,34.8 v1(18.45,33.73) 18.54,33.64 R75.1
  TOP w0.635: C32.1 23.1,87.83 22.54,88.39 C29.1 21.59,88.79 20.32,90.06 20.32,95.5 PM1.6
  LAYER3 w0.254: v1(26.99,5.84) 26.99,6.62 v1(20.41,13.21)
  BOTTOM w0.254: v1(20.14,87.78) 19.49,87.13 19.49,79.93 19.54,79.88 19.54,68.31 19.44,68.21 19.44,67.62 19.54,67.52 19.54,60.64 19.59,60.59 19.59,51.84 19.54,51.79 19.54,50.19 18.8,49.45 v1(18.8,44.7) 18.8,43.87 16,41.07 16,38.1 16.36,37.74 16.36,35.83 v1(18.45,33.73) 21.34,30.85 21.34,24.38 20.41,23.46 v1(20.41,13.21) ; SW8.5 36.2,7.87 v1(39.88,7.87)
5V: length 135.2
  TOP w0.254: 41.83,60.71 44.7,60.71 46.23,62.23 47,62.23 U32.1 47.19,63.45 C111.1 ; 41.83,60.71 41.83,61.72 40.39,61.72 ; 41.83,60.71 C69.1 ; C84.1 40.78,35.17 40.17,35.78 U25.1 41.43,36.45 42.06,35.81 44.96,35.81 v1(45.97,34.8) ; C59.1 40.91,79.02 U20.1 39.01,79.63 38.72,79.34 33.6,79.34 33.52,79.25 ; C64.1 40.78,70.01 40.17,70.62 U21.1 33.64,71.25 33.52,71.37 ; 40.39,61.72 40.17,61.94 U22.1 ; 40.39,61.72 33.52,61.72 ; v1(45.97,43.69) C79.1 40.78,44.42 40.17,45.03 U24.1 36.32,45.72 35.05,46.99 35.05,50.77 34.52,51.31 ; 34.52,51.31 40.39,51.31 40.78,51.7 C74.1 41.83,52.58 41.83,53.45 40.8,54.48 U23.1 ; 34.52,51.31 33.52,52.31
  TOP w0.635: C55.1 31.75,88.26 v1(31.75,87.14) 32.14,86.74 C57.1 33.52,52.31
  LAYER2 w0.254: v1(45.97,34.8) v1(45.97,43.69)
  BOTTOM w0.635: PM3.6 31.75,96.9 v1(31.75,87.14)
5V_ISO: length 746.6
  TOP w0.254: v1(14.05,71.88) 14.05,70.76 14.45,70.36 C98.1 14.97,70.32 15.73,69.56 15.73,66.8 ; U21.8 29.43,70.07 30.37,69.13 C65.1 31.5,69.09 31.75,69.34 ; 10.16,48.64 9.91,48.39 9.91,41.66 10.47,41.09 11.04,41.09 ; 10.16,48.64 9.65,49.15 v1(9.65,56.84) 9.65,58.93 14.48,63.75 15.73,63.75 15.73,66.8 ; 10.16,48.64 U17.4 ; v1(114.81,11.81) 114.19,11.19 C44.1 111.51,12.45 110.62,13.34 U1.8 ; U29.8 157.35,44.83 159.5,42.68 C45.1 ; 11.04,41.09 11.04,40.44 ; 11.04,41.09 ADC1.5 ; U5.8 156.82,35.18 159.22,32.78 C46.1 159.26,34.04 v1(158.75,34.54) ; 31.75,36.58 31.62,36.45 U25.8 ; U6.8 84.96,13.46 83.57,13.46 83.31,13.72 v1(82.04,13.72) 82.04,15.46 82.45,15.86 C52.1 ; 15.73,66.8 U16.4 ; v1(74.68,51.56) 74.68,50.29 75.06,49.91 76.2,49.91 ; U7.8 57.77,12.83 57.63,12.69 C53.1 55.61,12.69 v1(55.12,12.19) ; 76.2,49.91 75.95,50.16 C109.1 ; 76.2,49.91 U31.8 ; 11.04,40.44 10.99,40.39 v1(9.65,40.39) 9.65,36.32 10.67,35.31 C96.1 ; 11.04,40.44 ADC1.6 ; C99.1 14.47,55.84 v1(13.47,56.84) ; 31.75,52.83 31.5,52.58 C75.1 30.37,52.62 29.43,53.56 U23.8 ; 31.75,60.71 C70.1 30.37,61.8 U22.8 ; 31.75,77.72 31.62,77.6 C60.1 30.49,77.64 29.55,78.58 U20.8 ; 31.75,43.43 31.62,43.56 C80.1 30.37,43.6 29.43,44.54 U24.8 ; U30.8 63.63,67.94 v1(64.26,68.58) 65.04,68.58 65.28,68.35 C106.1 ; C100.1 C95.1
  TOP w0.635: v1(47.75,86.36) 47.75,87.12 44.2,90.68 C100.1 41.03,90.64 40.06,89.66 36.58,89.66 36.07,90.17 31.08,90.17 30.07,89.17 30.07,87.12 31.75,85.45 v1(31.75,83.91) 31.75,35.84 30.37,34.46 C85.1 30.37,32.12 33.53,28.96 v1(39.88,28.96) ; C33.1 13.45,87.71 12.89,88.26 C28.1 ; v1(120.89,43.95) C107.1 113.79,44.96 112.65,46.1 U4.8 ; PM2.6 10.41,95.76 10.41,90.18 11.94,88.66 C28.1 ; C28.1 v1(10.67,88.26) ; v1(160.27,44.2) C45.1
  LAYER2 w0.635: v1(64.26,68.58) 64.26,64.52 72.39,56.39 72.39,53.85 v1(74.68,51.56) ; v1(114.81,11.81) 115.78,11.81 115.83,11.86 v1(121.41,11.86) ; v1(160.27,44.2) 157.73,41.66 131.83,41.66 129.53,43.95 v1(120.89,43.95)
  LAYER3 w0.254: v1(13.47,56.84) v1(9.65,56.84) ; 164.08,34.54 v1(158.75,34.54) ; 55.12,16.84 v1(55.12,12.19)
  LAYER3 w0.635: v1(10.67,88.26) 10.67,87.12 13.88,83.91 ; v1(160.27,44.2) 160.27,45.85 160.91,46.48 163.45,46.48 164.08,45.85 164.08,12.19 152.91,1.02 141.61,1.02 140.97,1.65 140.97,9.4 138.5,11.86 v1(121.41,11.86) ; R74.3 27.78,20.03 30.96,16.84 45.21,16.84 ; 45.21,16.84 45.21,23.62 v1(39.88,28.96) ; 45.21,16.84 78.92,16.84 v1(82.04,13.72) 83.95,11.81 v1(114.81,11.81) ; v1(14.05,71.88) 14.05,83.74 13.88,83.91 ; v1(47.75,86.36) 48.44,85.67 48.44,70.43 50.93,67.94 63.62,67.94 v1(64.26,68.58) ; 13.88,83.91 v1(31.75,83.91)
  BOTTOM w0.254: 12.02,20.03 11.76,20.28 11.76,28 9.14,30.62 9.14,38.86 9.65,39.37 v1(9.65,40.39) ; 12.02,20.03 R74.3 ; 12.02,20.03 11.43,19.44 11.43,9.91 J7.2
  BOTTOM w0.635: U26.8 121.79,105.11 118.29,101.6 106.05,101.6 105.41,100.97 105.41,63.75 102.11,60.45 102.11,47.88 102.74,47.24 117.6,47.24 v1(120.89,43.95)
18V_G1: length 62.2
  TOP w0.635: D5.1 v1(90.42,90.81) 90.42,89.17 91.69,87.9 C21.1 ; C36.1 108.71,104.14 109.35,103.5 U8.8 v1(111.13,105.92) ; v1(90.42,83.69) D10.1
  LAYER2 w0.635: v1(111.13,105.92) 109.86,107.19 100.33,107.19 90.42,97.28 v1(90.42,90.81)
  BOTTOM w0.635: v1(90.42,83.69) v1(90.42,90.81)
18V_G3: length 82.3
  TOP w0.635: v1(132.59,106.93) 133.74,105.79 U9.8 131.83,103.5 131.19,104.14 C37.1 ; v1(89.15,86.87) 88.18,86.87 87.55,86.23 D11.1 ; D6.1 88.06,93.09 88.18,93.22 v1(89.15,93.22) 90.31,93.22 91.69,91.83 C22.1
  LAYER2 w0.635: v1(89.15,93.22) 89.15,97.54 100.84,109.22 130.3,109.22 v1(132.59,106.93)
  BOTTOM w0.635: v1(89.15,93.22) v1(89.15,86.87)
18V_G5: length 109.5
  TOP w0.635: C38.1 159.21,106.43 160.15,105.49 v1(160.15,104.52) 159.13,103.5 U10.8 ; D12.1 86.79,88.52 86.91,88.39 86.94,88.39 v1(87.2,88.14) ; C23.1 90.42,95.25 90.17,95.5 v1(87.2,95.5) D7.1
  LAYER2 w0.635: v1(87.2,95.5) 87.2,97.1 102.87,112.78 149.35,112.78 157.61,104.52 v1(160.15,104.52)
  BOTTOM w0.635: v1(87.2,95.5) v1(87.2,88.14)
18V_G7: length 68.6
  TOP w0.254: C24.1 58.04,79.12 59.18,77.98 59.18,70.15 59.74,69.6 85.67,69.6 86.56,68.71 86.56,66.97 86.82,66.71 88.14,66.71
  TOP w0.635: D13.1 v1(59.94,90.17) 58.93,90.17 57.23,88.47 57.23,82.04 58.04,81.23 C24.1 ; 87.76,65.41 88.14,65.78 C39.1 ; D8.1 v1(59.94,84.33)
  BOTTOM w0.635: v1(59.94,90.17) v1(59.94,84.33)
18V_GL: length 159.5
  TOP w0.635: D9.1 v1(60.96,86.61) ; D14.1 v1(60.96,92.46) 58.93,92.46 56.21,89.74 56.21,79.25 57.91,77.55 C25.1 52.58,76.2 52.32,75.95 52.32,46.48 55.63,43.18 63.12,43.18 65.02,41.27 C43.1 65.02,38.02 64.9,37.9 U15.8 ; v1(141.73,87.63) 140.76,87.63 140.25,88.14 C41.1 135.38,86.75 134.1,85.47 U13.8 ; U14.8 156.2,85.47 157.48,86.75 C42.1 161.59,88.14 162.1,87.63 v1(163.07,87.63) ; v1(118.87,87.63) 117.9,87.63 117.39,88.14 C40.1 113.03,86.87 111.63,85.47 U12.8
  LAYER2 w1.27: v1(60.96,86.61) 62.5,85.07 98.79,85.07 101.6,87.88 104.14,87.88
  BOTTOM w0.635: v1(60.96,86.61) v1(60.96,92.46)
GND: length 459.2
  TOP w0.254: C64.2 39.23,68.11 40.17,67.17 U22.4 U22.3 ; U3.8 81.79,76.86 ; 81.79,76.86 81.79,76.45 80.77,75.44 C16.2 ; 81.79,76.86 U3.9 ; U25.4 v1(37.03,40.26) 37.03,39.48 37.08,39.43 37.08,35.31 37.97,34.42 C84.2 ; U25.4 41.71,40.26 42.21,40.77 C83.2 ; U25.4 U25.3 41.8,38.99 42.05,39.24 R69.2 ; C74.2 38.47,52.58 38.2,52.31 v1(37.03,52.31) ; C20.1 92.21,78.5 92.2,78.49 R10.1 R13.2 ; U21.4 U21.3 41.55,73.79 43.17,72.17 C112.2 ; U21.4 39.54,75.06 38.71,75.89 38.71,77.6 ; U21.4 41.43,75.06 41.94,75.56 C63.2 ; U23.3 U23.4 ; U23.3 41.81,57.02 43.17,55.66 C114.2 ; U23.3 38.91,57.02 38.56,57.38 v1(37.03,57.38) ; U23.4 40.8,58.29 41.82,59.31 C73.2 ; U23.4 40.17,59.73 39.23,60.67 C69.2 38.53,60.71 38.48,60.76 v1(37.03,60.76) ; v1(37.02,82.3) 38.91,82.3 39.04,82.17 U20.3 U20.4 40.39,83.53 40.39,84.07 41.4,85.09 44.2,85.09 44.59,84.7 C58.2 44.61,83.93 R39.2 ; C113.2 43.17,63.54 41.43,65.28 U22.3 ; v1(37.08,49.78) 37.34,49.53 U24.4 ; 38.71,77.6 C59.2 ; 38.71,77.6 37.08,77.6 v1(37.03,77.65) ; U24.4 41.94,49.53 42.66,50.25 C78.2 42.77,50.18 R63.2 ; U24.4 U24.3 ; C79.2 38.35,43.69 v1(37.08,42.42) ; C68.2 42.34,67.06 41.83,66.55 40.8,66.55 ; U22.3 v1(37.08,65.28)
  TOP w0.381: C110.2 48.78,58.97 49.15,59.33 U32.3 49.15,62.84 49.03,62.95 C111.2 49.03,66.28 46.99,68.33 41.95,68.33 41.38,67.76 41.38,67.13 40.8,66.55 U22.4 38.35,66.55 v1(37.08,65.28)
  TOP w0.635: v1(69.34,72.14) 76.13,72.14 ; 76.13,72.14 76.19,72.19 R9.1 75.04,77.09 C17.2 74.26,77.84 73.15,78.94 73.15,81.28 73.79,81.91 C18.2 ; 76.13,72.14 80.77,72.14 ; C16.2 80.77,72.14 ; 80.77,72.14 87.88,72.14 88.02,72.28 C19.1 93.47,74.17 95.25,75.95 95.25,77.98 94.73,78.5 C20.1 ; 139.19,73.28 136.78,73.28 133.74,76.32 133.74,77.85 133.36,78.23 132.46,78.23 131.32,79.38 131.32,86.11 132.33,87.12 C41.2 ; C25.2 v1(68.07,76.2) 68.83,76.2 69.6,75.44 R14.1 v1(68.07,74.68) ; C42.2 154.43,86.79 153.92,86.28 153.92,79.4 155.47,77.85 155.83,77.85 155.83,75.31 157.86,73.28 161.29,73.28 ; Q8.3 U15.5 61.72,28.7 61.21,29.21 61.21,37.26 61.98,38.02 C43.2 ; C54.2 2.03,97.21 2.78,96.46 C31.2 C30.2 C56.2 ; D14.2 67.99,92.46 TX1.2 v1(70.03,92.53) ; D18.1 52.83,3.43 53.47,2.79 63.37,2.79 64.01,3.43 J5.2 ; D17.1 78.11,2.67 77.98,2.54 ; v1(37.47,88.52) C55.2 35.06,88.51 C57.2 ; C40.2 109.98,86.79 108.71,85.52 108.71,79.9 110.77,77.85 111.13,77.85 111.13,75.56 113.41,73.28 116.59,73.28 ; 2.03,105.55 2.03,106.3 2.67,106.93 3.42,106.93
  TOP w1.27: C5.2 43.15,110.52 42.42,111.25 PM3.1 PM1.1 PM2.1 9.65,111.25 5.59,107.19 3.67,107.19 2.03,105.55 C26.2 C27.2 C54.2
  BOTTOM w0.254: C4.2 91.16,7.47 J4.2 ; 37.03,65.79 37.08,65.74 v1(37.08,65.28) ; 37.03,50.55 37.08,50.5 v1(37.08,49.78) ; v1(37.08,42.42) 37.08,42.88 37.03,42.93
  BOTTOM w0.635: PM3.1 35.31,109.35 35.31,97.92 PM3.7 37.34,92.07 37.34,87.88 ; v1(37.03,40.26) v1(37.03,52.31) v1(37.03,57.38) v1(37.03,60.76) v1(37.03,77.65) 37.03,78.62 37.02,78.63 v1(37.02,82.3) 37.02,83.22 37.34,83.54 37.34,87.88 ; 37.34,87.88 37.47,88.01 v1(37.47,88.52)
GND_SIGNAL: length 710.5
  TOP w0.254: C52.2 85.07,17.41 U6.5 85.08,18.41 C50.2 ; R61.1 27.93,49.53 ; 27.93,49.53 U24.5 ; 27.93,49.53 27.93,51.05 ; U17.11 19.27,48.64 19.56,48.93 19.56,51.21 v1(18.45,52.31) 16.92,53.85 C99.2 ; R71.2 C88.2 23.89,28.09 v1(24.3,27.69) ; 27.55,43.56 26.94,44.18 C82.1 ; 27.55,43.56 27.55,42.55 v1(27.69,42.42) ; 27.55,43.56 C80.2 28.82,42.3 29.43,41.69 U25.5 26.74,40.26 26.65,40.35 R67.1 ; 29.5,16.46 29.37,16.59 29.37,16.78 ; C75.2 27.93,52.58 ; 27.93,52.58 27.93,53.83 27.79,53.98 C77.1 ; 27.93,52.58 27.93,51.05 ; v1(10.92,30.73) 11.26,30.39 U27.4 12.18,29.22 12.7,28.7 C102.1 ; U1.5 108.62,9.52 108.74,9.64 C47.2 C44.2 v1(111.51,8.13) ; 27.46,68.33 27.46,69.09 ; 27.46,68.33 27.71,68.07 v1(28.96,68.07) 29.43,67.6 U22.5 29.3,66.68 R49.1 ; 27.46,68.33 26.95,67.82 24.13,67.82 23.11,66.8 U16.11 17.27,66.8 16.52,67.55 C98.2 ; 27.46,69.09 27.46,69.81 27.38,69.81 27.06,70.13 C67.1 ; 27.46,69.09 C65.2 ; U28.2 36.07,13.97 35.56,14.48 32.02,14.48 31.52,14.99 v1(30.73,14.99) ; v1(23.62,77.22) 24,77.6 26.92,77.6 ; 27.93,51.05 26.92,51.05 v1(26.67,50.8) ; C72.1 27.06,61.07 27.43,60.71 C70.2 28.82,60.08 28.96,59.94 v1(28.96,59.44) 29.21,59.18 29.21,58.51 U23.5 R55.1 ; v1(20.14,33.73) 20.14,34.8 19.63,35.31 C97.2 ; ADC1.17 17.04,41.74 ; 17.04,41.74 17.04,43.59 16.94,43.69 ; 17.04,41.74 ADC1.4 ; 16.94,43.69 ADC1.20 ; 16.94,43.69 v1(16.76,43.87) ; 26.92,77.6 26.94,77.61 C62.1 R37.1 ; 26.92,77.6 C60.2 ; v1(27.18,76.45) 27.06,76.34 R43.1 28.22,75.18 28.22,75.06 U21.5 ; C87.1 26.56,35.78 27.91,34.42 C85.2 28.82,33.41 29.46,32.77 v1(29.46,30.73) ; v1(33.53,11.94) 33.53,12.14 33.1,12.57 C103.2 ; C49.2 157.23,30.23 v1(156.46,29.46) ; C49.2 C46.2 ; C49.2 156.49,31.23 156.35,31.37 U5.5 ; U29.5 156.63,41.02 156.74,41.14 C104.2 C45.2 161.01,41.14 162.81,42.94 v1(162.81,44.96) ; U15.3 55.64,31.24 54.37,29.97 R73.2 C89.2 44.84,27.78 41.7,24.64 D22.1 ; U20.5 v1(29.55,85.51) ; C53.2 56.93,14.24 57.54,14.85 57.54,15.55 58.63,16.64 U7.5 ; ADC1.8 11.69,39.14 11.18,38.63 v1(11.18,36.58) 12.19,36.58 12.74,36.03 12.74,35.95 13.35,35.34 C96.2 ; C95.2 C100.2
  TOP w0.381: v1(56.39,21.59) 56.99,20.99 56.99,19.46 58.15,18.29 C51.2 59.18,18.03 U7.5 ; C52.2 82.44,17.41 81.03,16 v1(81.03,10.67)
  TOP w0.635: v1(120.92,42.41) C107.2 C48.2 111.65,42.29 U4.5 ; v1(100.33,80.52) 100.46,80.39 U12.3 ; v1(41.4,11.94) 41.54,11.8 R78.2 R79.2 ; C32.2 24.65,88.38 C29.2 24.64,88.79 25.76,89.91 26.29,89.91 v1(26.29,91.06) ; v1(30.73,14.99) 30.23,15.49 D23.1 29.5,16.65 29.37,16.78 D24.1 D25.1 D26.1 ; v1(100.46,98.3) 100.58,98.43 U8.3 ; U9.3 v1(122.55,98.43) ; v1(32.77,91.19) 33.74,91.19 33.99,91.44 38.1,91.44 38.86,90.68 C100.2 ; v1(122.81,80.39) U13.3 ; v1(80.64,59.56) 79.62,59.56 78.86,60.32 79.23,60.32 81.79,62.89 81.79,67.58 v1(82.87,68.66) 68.84,68.66 66.21,66.03 C106.2 65.28,64.77 64.76,64.25 C105.2 62.51,64.25 62.4,64.13 U30.5 ; v1(14.99,90.42) C28.2 15,88.25 C33.2 ; v1(80.64,53.72) U31.5 77.33,53.72 C108.2 C109.2 ; D22.1 D21.1 D20.1 40.67,17.39 40.8,17.26 D19.1 40.64,15.33 v1(40.64,13.72) ; v1(145.16,80.39) U14.3 ; U10.3 v1(144.91,98.43)
  LAYER2 w0.254: J1.20 4.32,57.66 ; 19.86,44.7 19.86,34.13 20.14,33.85 v1(20.14,33.73) ; v1(122.55,98.43) 124.08,98.43 ; v1(16.76,43.87) 16.76,44.7 ; 11.18,37.52 v1(11.18,36.58) ; 27.06,44.7 26.9,44.7 26.9,44.27 26.9,43.21 v1(27.69,42.42)
  LAYER2 w0.381: 80.52,2.03 81.03,2.54 v1(81.03,10.67) ; v1(56.39,21.59) 55.63,21.59 53.85,19.81 53.85,3.56 55.37,2.03
  LAYER2 w0.635: 110.49,2.03 111.51,1.02 152.91,1.02 164.08,12.19 164.08,27.94 162.31,29.72 ; 110.49,2.03 41.15,2.03 ; 110.49,2.03 111.51,3.05 v1(111.51,8.13) ; v1(156.46,29.46) 157.15,30.15 161.87,30.15 162.31,29.72 ; v1(80.64,53.72) v1(80.64,59.56) ; 162.81,41.15 161.87,40.21 131.24,40.21 129.04,42.41 v1(120.92,42.41) ; 162.81,41.15 v1(162.81,44.96) ; 162.81,41.15 164.08,39.88 164.08,31.5 162.31,29.72
  LAYER2 w1.27: 32.26,81.03 33.47,79.81 71.94,79.81 73.73,81.6 99.24,81.6 v1(100.33,80.52)
  LAYER3 w0.254: J7.10 16.47,15.03 R74.1
  LAYER3 w0.635: v1(100.33,80.52) 100.33,73.91 95.08,68.66 v1(82.87,68.66)
  BOTTOM w0.635: U26.5 125.6,105.11 126.49,104.22 126.49,100.33 124.59,98.43 v1(122.55,98.43) 124.46,100.33 C94.2
  BOTTOM w1.27: v1(100.33,80.52) 100.33,81.81 100.46,81.93 v1(100.46,98.3)
VIN: length 103.1
  TOP w0.254: F1.2 R33.1 51.31,86.63 ; U3.1 77.64,80.36 76.19,78.91 R8.1 76.19,78.83 76.96,78.05 76.96,76.2 77.72,75.44 C16.1
  TOP w0.635: C54.1 5.08,97.21 4.33,96.46 C31.1 C30.1 C56.1 ; TX1.1 72.85,94.53 74.3,93.09 v1(74.3,89.03) ; R8.1 75.67,79.39 C17.1 v1(74.3,80.39)
  TOP w1.27: C54.1 C27.1 C26.1 7.11,105.16 10.67,108.71 PM2.2 PM1.2 PM3.2 C5.1
  BOTTOM w0.254: 39.61,108.71 C5.1
  BOTTOM w0.635: v1(74.3,80.39) v1(74.3,89.03) 74.3,92.33 82.3,100.33 v1(84.58,100.33)
  vias: v1(38.1,102.62) v1(38.1,101.6) v1(39.12,102.62) v1(39.12,101.6) v1(40.13,102.62) v1(40.13,101.6) v1(53.85,81.03) v1(53.85,72.9) v1(54.36,73.91) v1(54.86,72.9) v1(55.37,73.91) v1(55.88,72.9) v1(56.39,73.91) v1(56.9,72.9) v1(60.96,56.64) v1(60.96,55.12) v1(62.23,56.64) v1(62.23,55.12) v1(63.5,56.64) v1(63.5,55.12)
ADC-IIN-3V: length 64.1
  TOP w0.254: v1(15.04,48.01) 16.35,46.69 U17.8 U17.9
  BOTTOM w0.254: v1(15.04,48.01) 15.04,45.47 14.78,45.21 13.33,45.21 13.02,45.52 13.02,54.95 14.26,56.18 14.26,60.93 17.27,63.95 17.27,70.1 12.95,74.42 2.58,74.42 2.58,82.04 5.33,82.04 J1.37
ADC-VIN: length 48.8
  TOP w0.254: R38.2 15.76,82.94 16.41,82.3 ; 16.41,82.3 v1(17.72,82.3) ; 16.41,82.3 C61.2 ; v1(14.97,69.1) 14.62,68.75 U16.1
  LAYER3 w0.254: v1(14.97,69.1) 14.97,74.16 17.72,76.9 v1(17.72,82.3)
  BOTTOM w0.254: v1(14.97,69.1) 14.19,69.1 13.95,69.34 5.89,69.34 5.33,68.78 5.33,65.02 6.1,64.26 7.4,64.26 8.13,63.53 8.13,53.12 7.84,52.83 J1.15
ADC-VPOT-3V: length 49.9
  TOP w0.254: U17.13 17.16,49.94 16.76,50.34 v1(16.76,50.62) 16.8,50.59 U17.14
  BOTTOM w0.254: J1.38 5.33,79.5 18.85,79.5 19.11,79.25 19.11,68.49 19.01,68.39 19.01,67.44 19.11,67.34 19.11,60.46 19.16,60.41 19.16,52.02 19.11,51.97 19.11,50.88 18.85,50.62 v1(16.76,50.62)
ADC_DSP4: length 55.9
  TOP w0.254: v1(13.46,59.18) 12.57,58.29 U17.1 ; C81.2 17.17,60.83 ; 17.17,60.83 17.74,60.83 18.29,60.29 v1(18.29,56.9) ; 17.17,60.83 17.17,61.98 R62.2
  LAYER3 w0.254: v1(18.29,56.9) 15.06,60.12 14.4,60.12 v1(13.46,59.18)
  BOTTOM w0.254: J1.35 18.2,78.23 18.45,77.98 18.45,76.91 18.54,76.82 18.54,66.9 18.45,66.82 18.45,57.84 18.29,57.68 v1(18.29,56.9)
ADC_VA: length 46.7
  TOP w0.254: v1(12.19,76.2) 12.19,77.32 13.36,78.49 16.41,78.49 16.41,79.25 ; R44.2 16.41,80.39 16.41,79.25 ; U16.7 v1(10.41,64.85) ; 16.41,79.25 C66.2
  LAYER3 w0.254: 9.24,66.64 9.08,66.8 2.54,66.8 2.54,54.36 J1.16 ; 9.24,66.64 9.24,65.24 9.63,64.85 v1(10.41,64.85) ; 9.24,66.64 12.19,69.59 v1(12.19,76.2)
ADC_VB: length 51.4
  TOP w0.254: 15.11,76.45 14.99,76.33 14.99,72.9 15.19,72.7 17.35,72.7 20.45,69.6 v1(22.1,69.6) ; 15.11,76.45 14.99,76.58 14.99,77.6 R50.2 ; 15.11,76.45 C71.2 ; U16.8 22.42,64.85 v1(23.52,63.75)
  LAYER3 w0.254: v1(23.52,63.75) 23.52,62.97 23.43,62.87 23.43,55.63 23.17,55.37 J1.17
  BOTTOM w0.254: v1(23.52,63.75) 23.52,66.53 22.1,67.95 v1(22.1,69.6)
ADC_VBOOST: length 51.5
  TOP w0.254: v1(16.52,57.15) C86.2 R68.2 ; U17.7 13.33,46.69 13.73,46.29 v1(13.73,45.99)
  BOTTOM w0.254: v1(13.73,45.99) 13.73,46.77 13.68,46.82 13.68,54.95 15.32,56.59 15.96,56.59 v1(16.52,57.15) 17.25,57.87 17.25,60.93 17.8,61.49 17.8,67.25 18.1,67.56 18.1,76.64 17.78,76.96 5.33,76.96 J1.36
ADC_VC: length 51
  TOP w0.254: U16.14 22.76,68.75 22.97,68.96 v1(23.75,68.96) 22.39,70.32 20.62,70.32 19.62,71.32 19.62,73.08 19.29,73.41 16.66,73.41 16.41,73.66 ; C76.2 16.41,73.66 ; 16.41,73.66 16.41,74.8 R56.2
  LAYER3 w0.254: v1(23.75,68.96) 21.83,67.04 21.83,56.37 21.34,55.88 16.26,55.88 14.26,57.87 8.85,57.87 7.62,56.64 5.33,56.64 J1.18
DC_LINK: length 4.5
  TOP w0.254: R88.2 140.97,106.68 142.01,107.72 C34.1
DSP_G1: length 166.9
  TOP w0.254: R17.1 98.55,104.77 98.93,105.16 v1(100.08,105.16)
  LAYER3 w0.254: v1(99.57,37.57) 18.02,37.57 15.49,35.05 J1.1
  BOTTOM w0.254: v1(100.08,105.16) 98.04,105.16 97.79,104.9 97.79,41.91 99.57,40.13 v1(99.57,37.57)
DSP_G2: length 154.1
  TOP w0.635: R25.1 v1(98.55,87.63)
  LAYER3 w0.254: v1(100.58,64.52) 98.55,64.52 96.27,66.8 58.93,66.8 46.48,54.36 16.76,54.36 11.43,49.02 6.1,49.02 5.33,48.26 5.33,46.74 5.08,46.48 3,46.48 2.48,45.96 2.48,36.64 J1.2
  LAYER3 w0.635: v1(98.55,87.63) 107.7,78.49 107.7,67.44 104.77,64.52 v1(100.58,64.52)
DSP_G3: length 187.9
  TOP w0.254: R19.1 v1(120.14,105.92)
  LAYER3 w0.254: J1.3 16.76,37.59 17.27,38.09 71.92,38.09 71.93,38.1 75.44,38.1 77.72,40.39 93.98,40.39 95.5,38.86 v1(98.3,38.86)
  BOTTOM w0.254: v1(120.14,105.92) 118.36,107.7 98.04,107.7 97.28,106.93 97.28,41.15 98.3,40.13 v1(98.3,38.86)
DSP_G4: length 154.9
  TOP w0.635: R27.1 120.76,85.98 119.38,84.6 v1(119.38,83.06)
  LAYER2 w0.254: v1(100.58,62.99) 95.04,62.99 84.12,52.07 76.2,52.07 75.74,51.61 75.74,40.43 v1(75.18,39.88)
  LAYER3 w0.254: J1.4 5.22,38.75 74.83,38.75 75.18,39.1 v1(75.18,39.88)
  LAYER3 w0.635: v1(100.58,62.99) 116.08,62.99 119.38,66.29 v1(119.38,83.06)
DSP_G5: length 207.7
  TOP w0.254: v1(138.94,104.01) R21.1
  LAYER3 w0.254: v1(96.77,39.88) 95.47,41.19 9.18,41.19 8.13,40.13 J1.5
  BOTTOM w0.254: v1(96.77,39.88) 96.01,40.64 96.01,49.28 96.77,50.04 96.77,107.19 98.04,108.46 125.48,108.46 129.92,104.01 v1(138.94,104.01)
DSP_G6: length 184.8
  TOP w0.635: R29.1 142.86,85.98 v1(141.48,84.6)
  LAYER3 w0.254: v1(100.58,61.47) 98.55,59.44 98.55,51.91 95.41,48.77 64.01,48.77 58.42,54.36 47.5,54.36 44.45,51.31 27.16,51.31 24.87,53.59 17.02,53.59 7.37,43.94 3.38,43.94 2.91,43.47 2.91,41.29 J1.6
  LAYER3 w0.635: v1(141.48,84.6) 141.48,64.01 138.94,61.47 v1(100.58,61.47)
DSP_G7: length 87.4
  TOP w0.254: R23.1 75.06,66.68 74.42,67.31 69.34,67.31 58.93,56.9 58.93,45.21 58.24,44.52 v1(57.4,44.52)
  LAYER3 w0.254: J1.7 9.4,42.67 10.67,43.94 15.24,43.94 16.26,42.93 19.3,42.93 20.9,44.52 v1(57.4,44.52)
DSP_G8: length 52.5
  TOP w0.254: v1(43.45,42.24) 50.71,42.24 51.56,41.39 R31.1
  LAYER3 w0.254: J1.8 5.33,41.4 8.38,41.4 8.64,41.66 42.87,41.66 v1(43.45,42.24)
GPIO-20: length 72.1
  BOTTOM w0.254: J1.27 12.19,68.07 12.49,67.78 12.49,44.2 12.74,43.94 14.73,43.94 14.99,43.69 14.99,9.91 15.38,9.51 15.38,5.96 J7.3
GPIO-21: length 74
  TOP w0.254: v1(3.56,8.87) 15.01,8.87 J7.4
  BOTTOM w0.254: J1.28 2.79,66.8 2.79,19.81 3.56,19.05 v1(3.56,8.87)
GPIO-22: length 89.8
  TOP w0.254: J7.5 17.78,3.05 11.43,3.05 6.6,7.87 2.79,7.87 1.02,9.65 1.02,71.46 1.44,71.88 5.33,71.88 J1.29
GPIO-23: length 79.8
  TOP w0.254: J1.30 1.52,68.07 1.52,11.43 3.3,9.65 16.76,9.65 J7.6
I_BOOST: length 88.5
  TOP w0.254: U7.7 58.12,14.1 57.49,13.46 56.13,13.46 55.88,13.72 v1(55.88,20.07) ; v1(18.8,36.83) 18.8,37.59 18.54,37.84 ADC1.11
  LAYER2 w0.254: v1(55.88,20.07) 55.88,4.83 56.39,4.32 66.8,4.32 TP7.1
  LAYER3 w0.254: v1(18.8,36.83) 19.35,36.28 47.8,36.28 53.34,30.73 53.34,22.61 v1(55.88,20.07)
I_BUCK: length 101.3
  TOP w0.254: v1(83.06,14.48) 83.44,14.86 U6.7 ; ADC1.12 20.32,38.49 21.04,37.78 21.04,35.12 21.34,34.82 v1(21.34,34.04)
  LAYER2 w0.254: TP8.1 92.96,3.81 84.58,3.81 83.06,5.33 v1(83.06,14.48)
  LAYER3 w0.254: v1(21.34,34.04) 36.83,34.04 53.34,17.53 80.01,17.53 v1(83.06,14.48)
I_L1: length 168.4
  TOP w0.254: v1(20.8,39.51) 19.87,40.44 ADC1.15 ; v1(107.19,43.94) 108.08,44.83 108.97,44.83 ; v1(112.01,30.48) v1(105.41,23.88)
  LAYER2 w0.254: v1(77.22,31.75) 73.72,35.25 v1(53.28,35.25)
  LAYER3 w0.254: v1(138.68,22.86) 138.68,17.53 TP3.1
  BOTTOM w0.254: v1(20.8,39.51) 23.85,36.46 52.07,36.46 v1(53.28,35.25) ; v1(77.22,31.75) 97.54,31.75 v1(105.41,23.88) ; v1(107.19,43.94) 106.64,43.39 106.64,35.86 v1(112.01,30.48) 134.37,30.48 138.68,26.16 v1(138.68,22.86)
I_L2: length 219.3
  TOP w0.254: U5.7 153.77,33.91 152.4,32.54 v1(152.4,29.46) ; ADC1.14 18.09,39.8 v1(16.91,39.8)
  LAYER3 w0.254: v1(152.4,29.46) 152.4,11.68 TP4.1
  BOTTOM w0.254: v1(16.91,39.8) 18.88,39.8 19.63,39.04 19.63,37.16 19.65,37.14 19.65,36.74 22.95,33.44 22.95,11.34 32.26,2.03 150.37,2.03 153.67,5.33 153.67,13.46 152.4,14.73 v1(152.4,29.46)
I_L3: length 202.6
  TOP w0.254: v1(16.74,33.78) 16.74,34.56 16.51,34.79 16.51,38.35 17.3,39.14 ADC1.13
  TOP w0.381: v1(153.16,44.58) 154.18,43.56 U29.7
  LAYER3 w0.254: v1(16.74,33.78) 17.7,34.74 42.73,34.74 49.02,28.45 49.02,22.86 53.9,17.98 116.02,17.98 142.75,44.7 152.91,44.7 153.16,44.45 ; 153.16,44.45 154.32,43.29 154.32,13.57 TP5.1 ; 153.16,44.45 v1(153.16,44.58)
I_L4: length 29.5
  TOP w0.254: JP3.3 TP9.1 ; U31.7 77.09,51.18 v1(76.71,50.8)
  LAYER2 w0.254: v1(76.71,50.8) 99.31,50.8 TP9.1
I_L5: length 94
  TOP w0.254: v1(50.55,70.1) 51.31,69.34 51.31,43.18 v1(54.36,40.13) ; v1(14.22,40.39) 14.22,39.12 13.6,38.49 ADC1.9 ; U30.7 60.16,66.68 59.18,67.66 v1(59.18,68.83)
  LAYER3 w0.254: v1(14.22,40.39) 15.49,40.39 15.75,40.64 21.84,40.64 22.93,39.55 53.78,39.55 v1(54.36,40.13) ; TP6.1 v1(59.18,68.83) 51.82,68.83 v1(50.55,70.1)
IA: length 89.2
  TOP w0.254: U1.7 105.54,12.06 104.9,11.43 v1(104.9,9.91)
  LAYER2 w0.254: v1(104.9,9.91) 102.11,12.7 102.11,41.91 JP3.1
  LAYER3 w0.254: v1(104.9,9.91) 116.08,9.91 119.38,13.21 140.97,13.21 142.24,11.94 142.24,5.33 143.51,4.06 TP2.1
IGBT_G8: length 4.7
  TOP w0.635: Q8.1 R32.2
IIN: length 180.5
  TOP w0.254: ADC1.16 21.28,41.09 21.74,41.56 ; R70.1 23.89,33.34 21.74,35.48 21.74,41.56 ; 21.74,41.56 v1(22.61,42.42)
  LAYER3 w0.254: 117.09,103.12 v1(122.43,103.12) ; 117.09,103.12 116.33,103.89 TP1.1 ; 117.09,103.12 116.08,102.11 77.47,102.11 74.17,98.81 47.99,98.81 v1(42.04,92.86)
  BOTTOM w0.254: v1(22.61,42.42) 25.65,39.37 41.28,39.37 42.04,40.13 v1(42.04,92.86) ; v1(122.43,103.12) 123.06,103.76 U26.7
LED1: length 57.1
  TOP w0.254: v1(30.67,22.25) 30.67,16.83 32,15.49 R80.1 ; J1.11 7.87,46.48 7.87,24.96 v1(10.59,22.25)
  LAYER3 w0.254: v1(30.67,22.25) v1(10.59,22.25)
LED2: length 60.2
  TOP w0.254: R81.1 v1(33.16,18.54) ; v1(3.81,32) 2.29,33.53 2.29,47.21 2.83,47.75 J1.12
  LAYER3 w0.254: v1(33.16,18.54) 33.16,29.07 30.23,32 v1(3.81,32)
LED3: length 61.4
  TOP w0.254: R82.1 v1(32.26,21.59)
  LAYER3 w0.254: v1(32.26,21.59) 32.26,25.34 27.88,29.72 3.56,29.72 2.03,31.24 2.03,49.02 5.33,49.02 J1.13
LED4: length 57.7
  TOP w0.254: R83.1 v1(30.85,24.64)
  LAYER3 w0.254: J1.14 2.09,50.29 1.52,49.72 1.52,29.72 2.27,28.97 26.52,28.97 v1(30.85,24.64)
LED5: length 65.9
  TOP w0.254: J1.31 8.38,71.37 8.38,28.35 21.24,15.49 R84.1
LED6: length 76.3
  TOP w0.254: R85.1 v1(21.84,18.54)
  LAYER3 w0.254: v1(2.54,18.8) 20.81,18.8 21.06,18.54 v1(21.84,18.54)
  BOTTOM w0.254: v1(2.54,18.8) 1.99,19.35 1.99,71.08 J1.32
LED7: length 64.3
  TOP w0.254: R86.1 17.78,21.59 8.89,30.48 8.89,73.41 J1.33
LED8: length 74.5
  TOP w0.254: v1(19.3,23.88) 20.07,24.64 R87.1
  LAYER3 w0.254: J1.34 1.05,72.68 1.05,25.81 1.31,25.55 17.63,25.55 v1(19.3,23.88)
LED9: length 81.6
  TOP w0.254: U28.1 38.85,13.72 v1(40.13,12.45)
  LAYER3 w0.254: J7.7 23.33,3.08 26.71,3.08 36.07,12.45 v1(40.13,12.45)
  BOTTOM w0.254: J1.9 8.38,43.43 8.38,6.1 11.43,3.05 20.32,3.05 J7.7
LED10: length 76.6
  TOP w0.254: U28.3 34.51,13.72 34.27,13.97 26.5,13.97 26.16,14.31 v1(21.84,14.31) ; J7.8 18.54,10.41 4.06,10.41 3.81,10.67 3.81,29.72 4.83,30.73 4.83,32.34 2.79,34.37 2.79,43.94 J1.10
  BOTTOM w0.254: v1(21.84,14.31) J7.8
SPI-ADC-VIN6: length 169.1
  TOP w0.254: ADC1.10 13.6,37.84 14.22,37.21 14.22,34.29 13.4,33.46 v1(10.65,33.46) ; v1(48.51,6.35) 46.48,8.38 v1(46.48,18.29)
  LAYER2 w0.254: JP3.2 98.55,44.45 98.55,42.67 101.35,39.88 101.35,11.94 v1(103.63,9.65)
  LAYER3 w0.254: v1(10.65,33.46) 11.2,32.91 22.75,32.91 23.31,33.47 36.36,33.47 46.48,23.35 v1(46.48,18.29) ; v1(103.63,9.65) 103.63,4.06 102.36,2.79 52.07,2.79 v1(48.51,6.35)
